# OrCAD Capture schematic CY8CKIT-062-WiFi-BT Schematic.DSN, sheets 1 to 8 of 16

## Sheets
1 01. Title Page: title: PSoC™ 6  Wi-Fi Bluetooth® Pioneer Kit; rev: 05; note: 630-60435-01
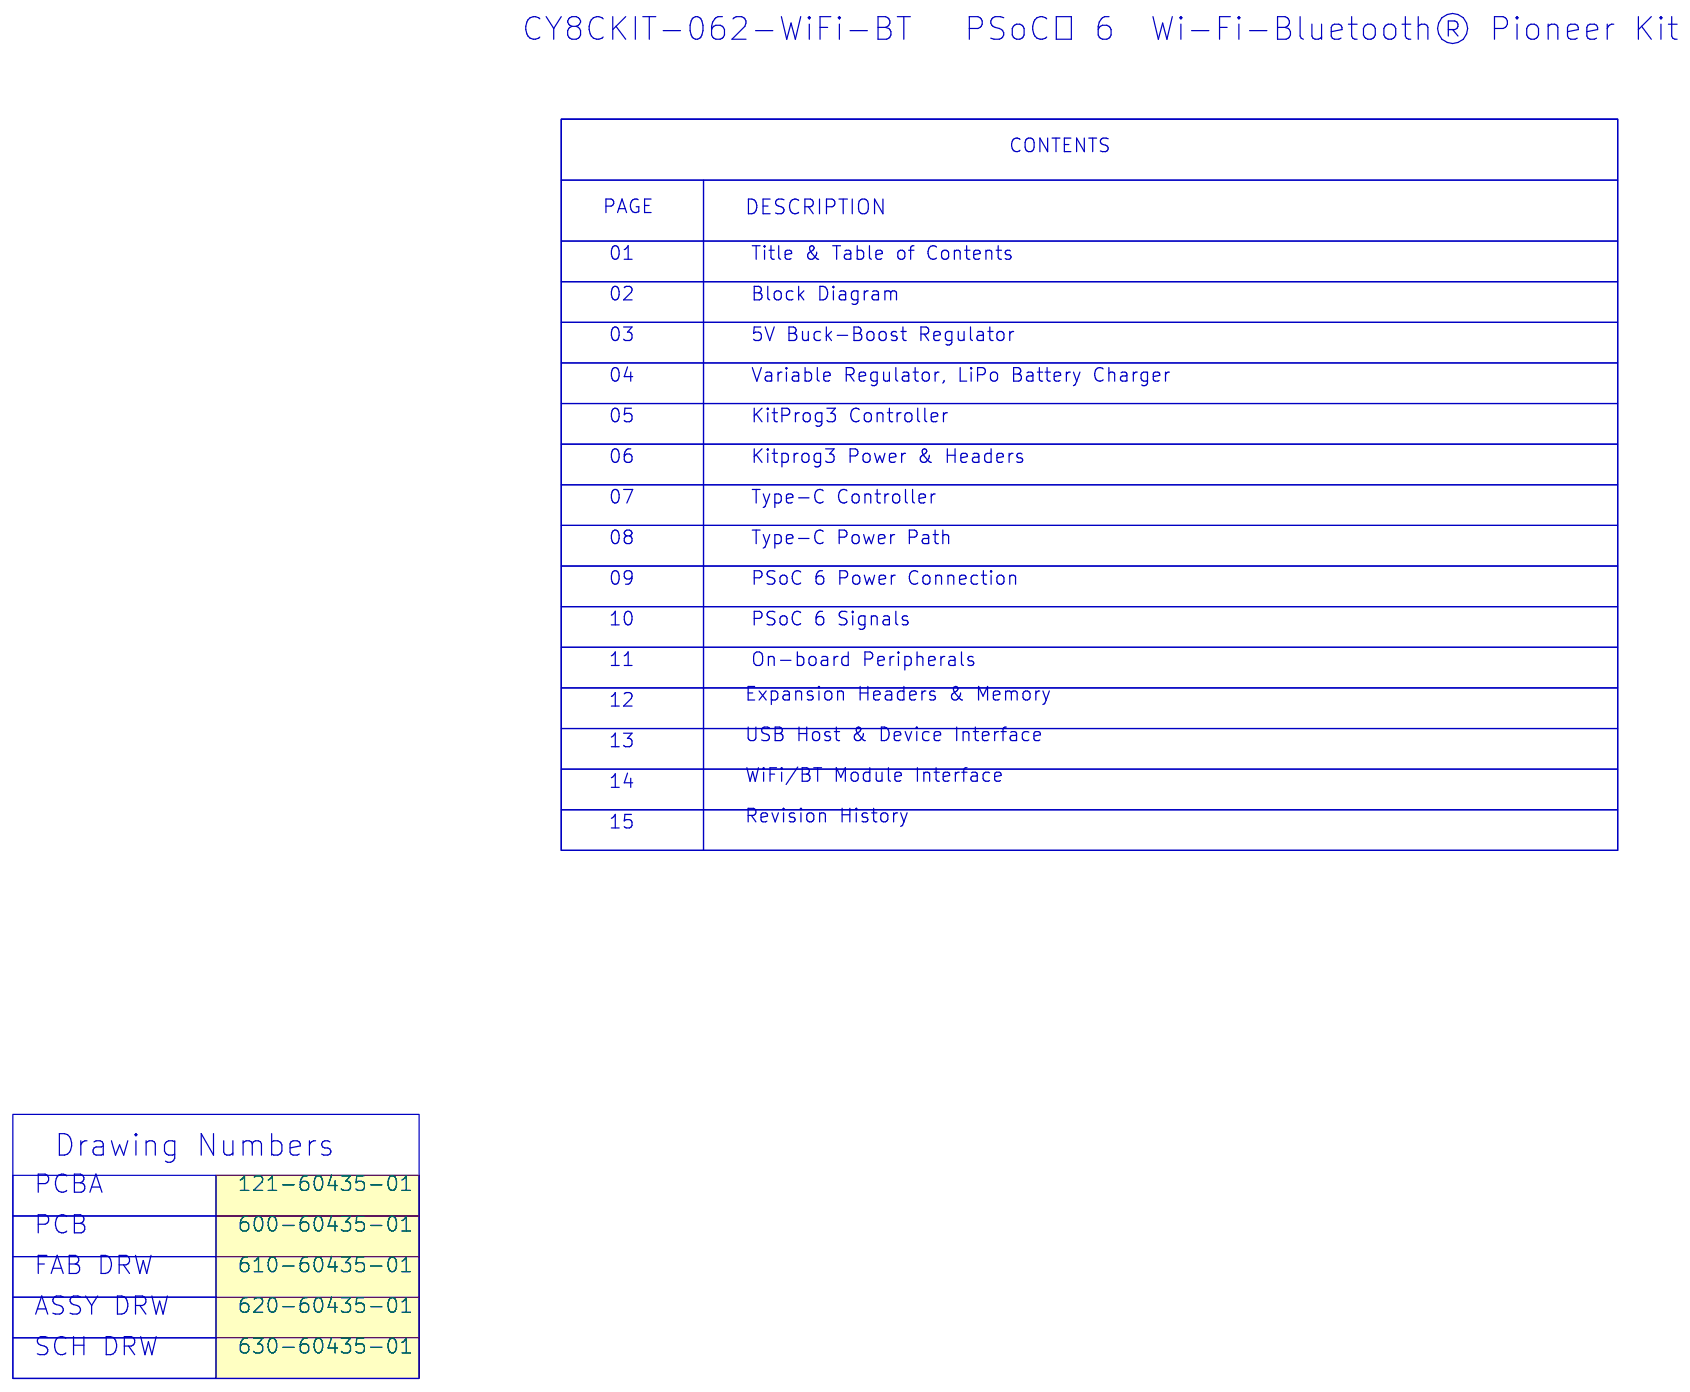
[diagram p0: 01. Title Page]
2 02. Block Diagram
3 04. Variable Regulator, Charger: size A4
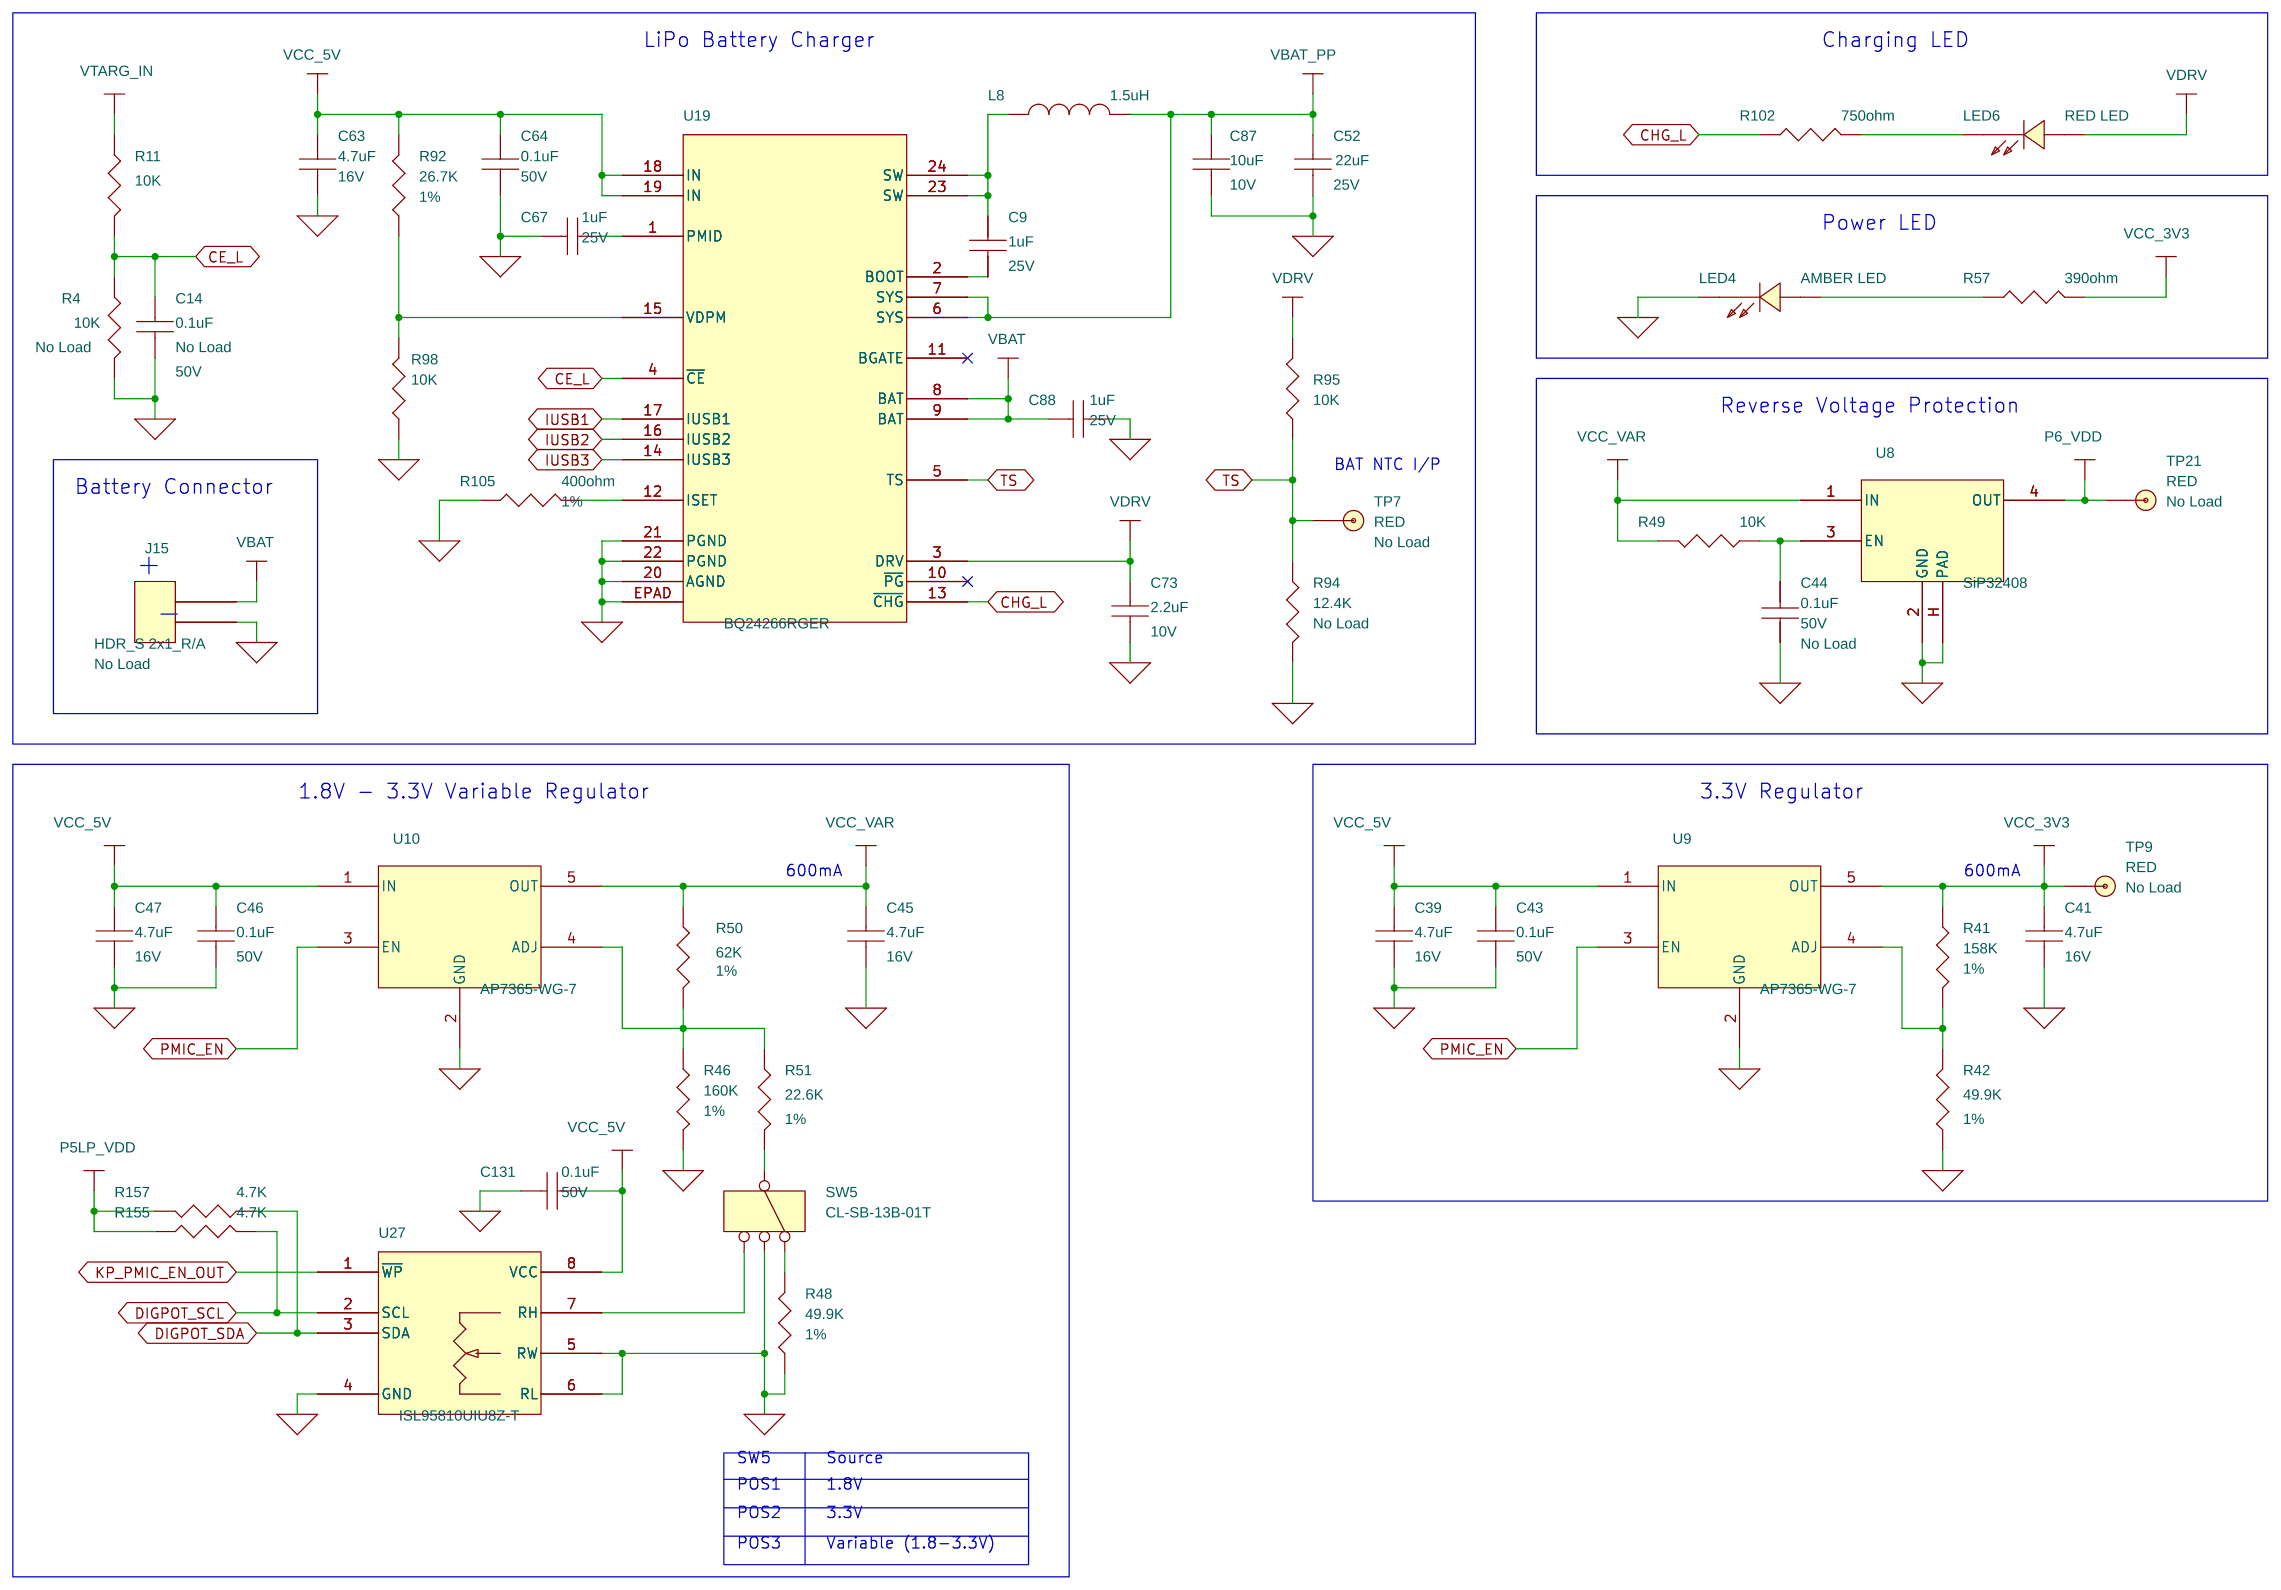
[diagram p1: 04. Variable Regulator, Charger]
4 05. KitProg3 Controller: size A4
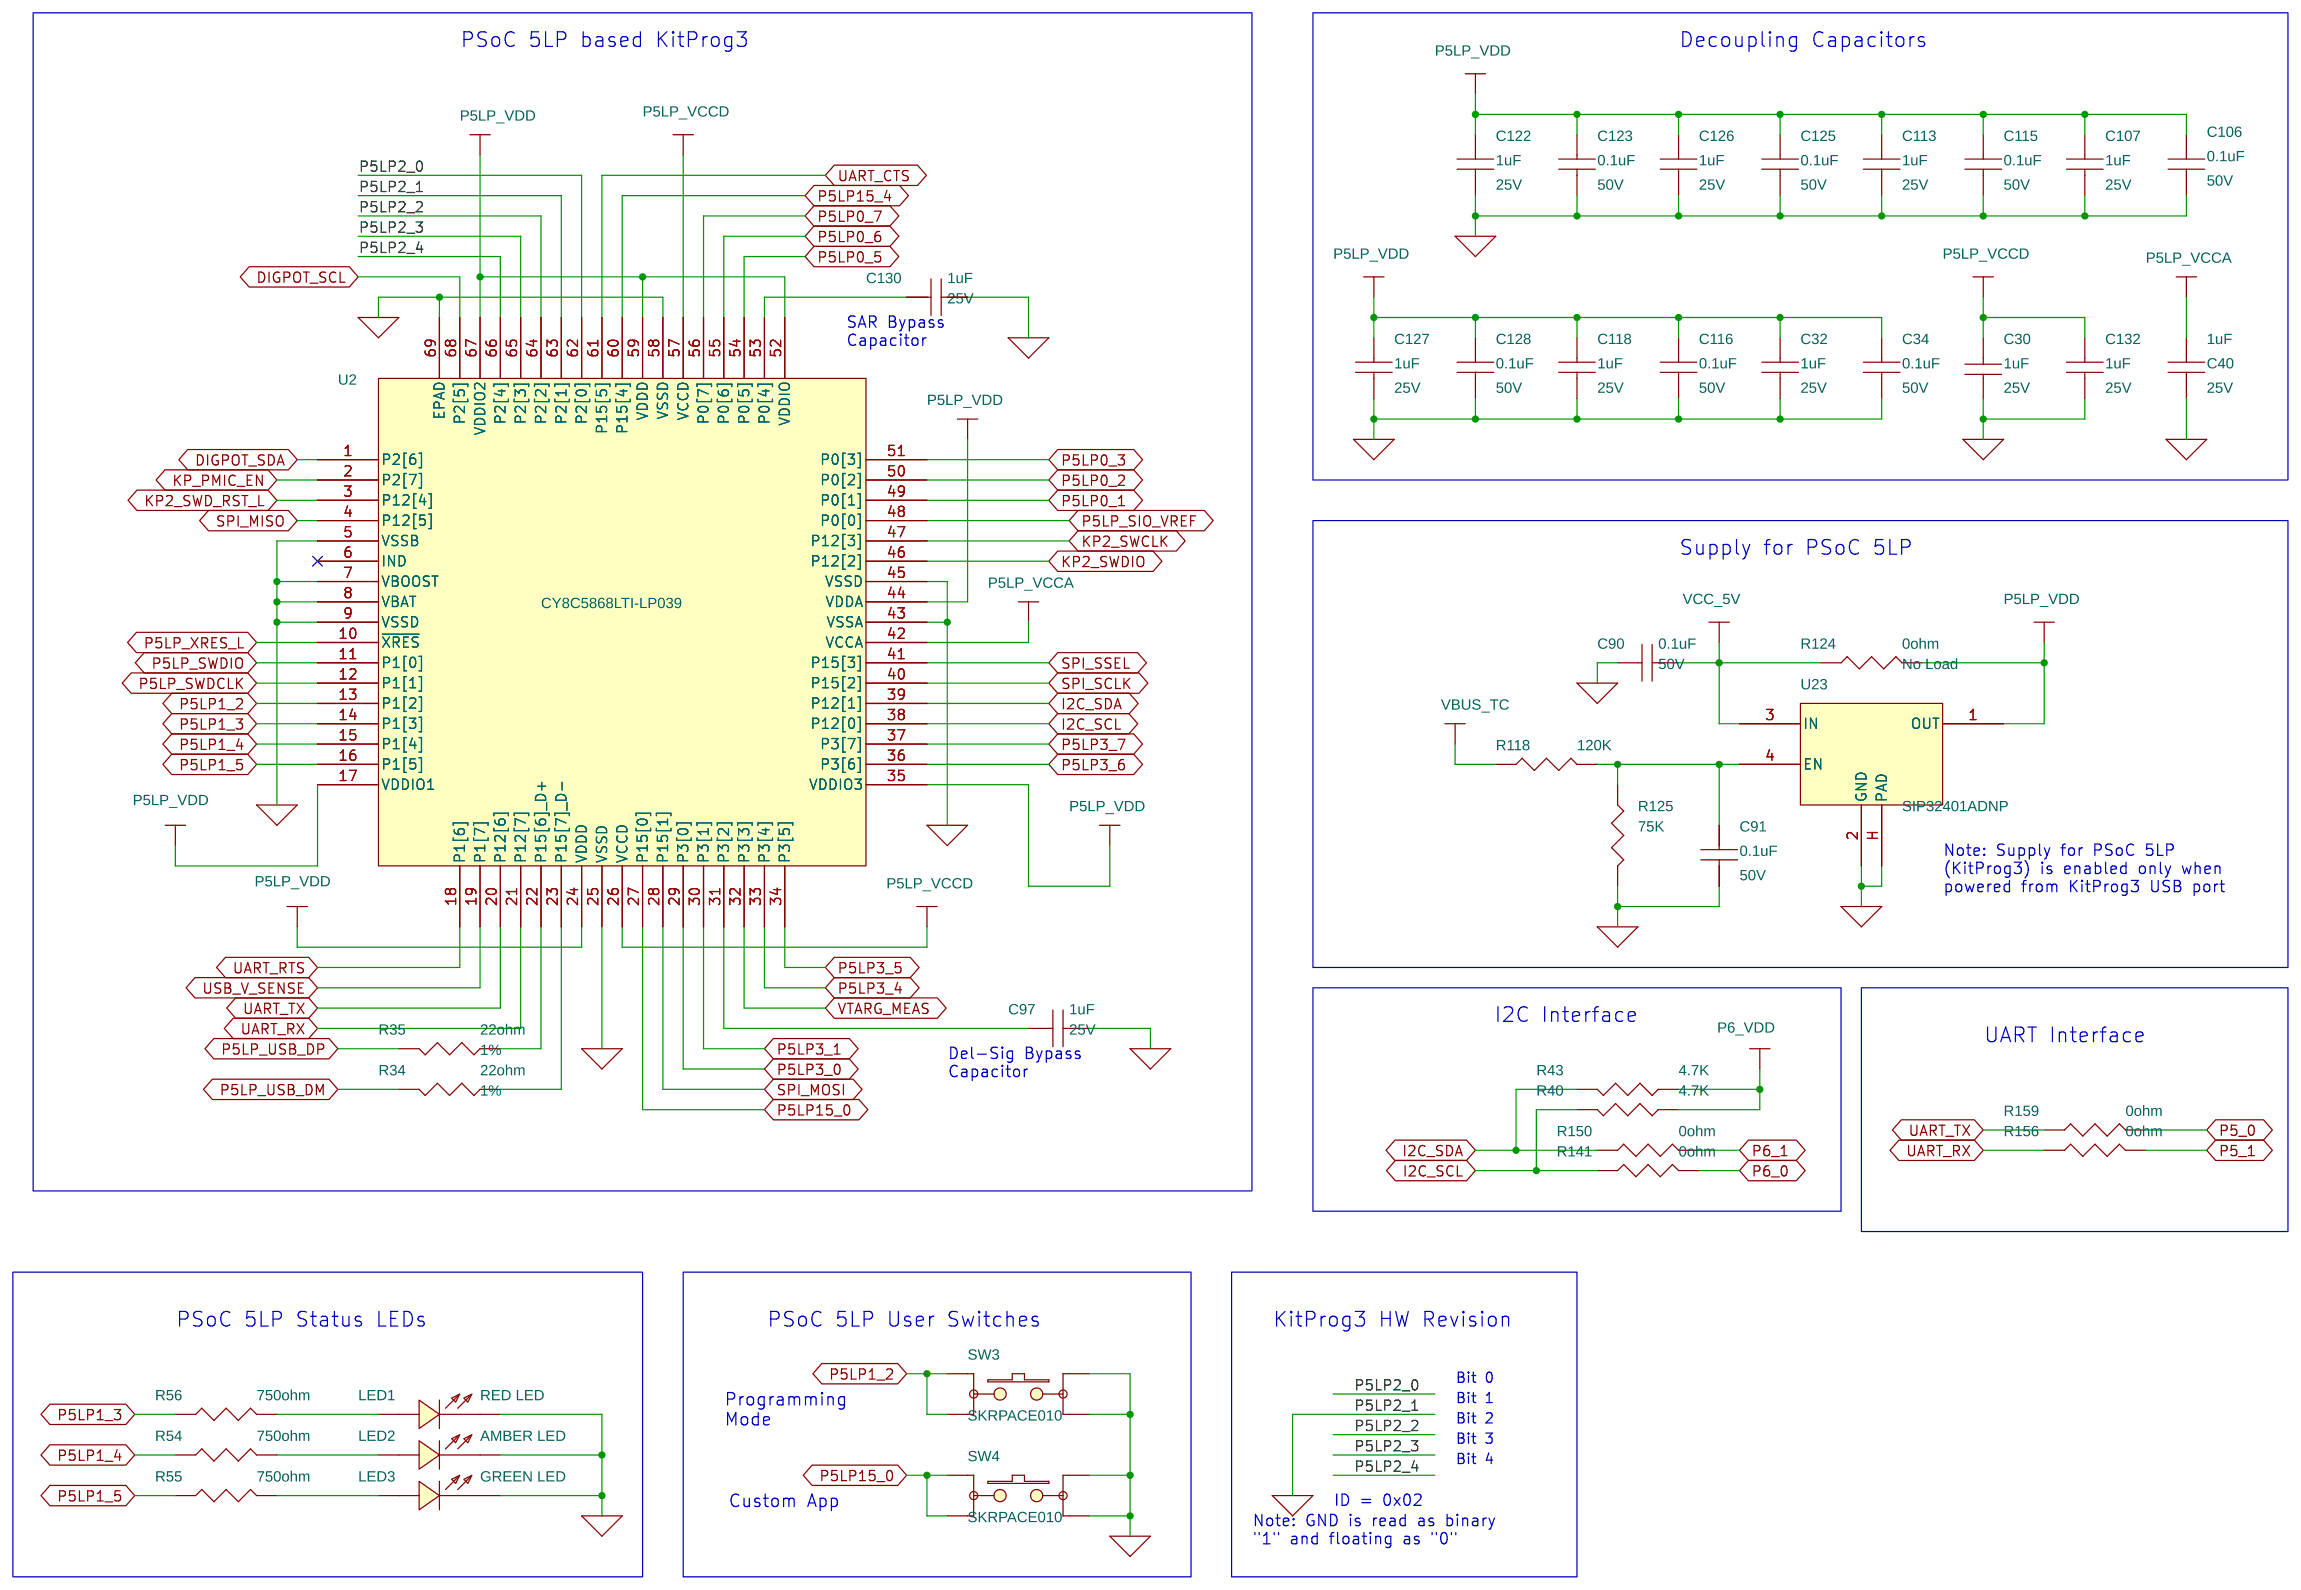
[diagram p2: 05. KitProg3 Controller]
5 06. Kitprog3 Power & Headers: size A4
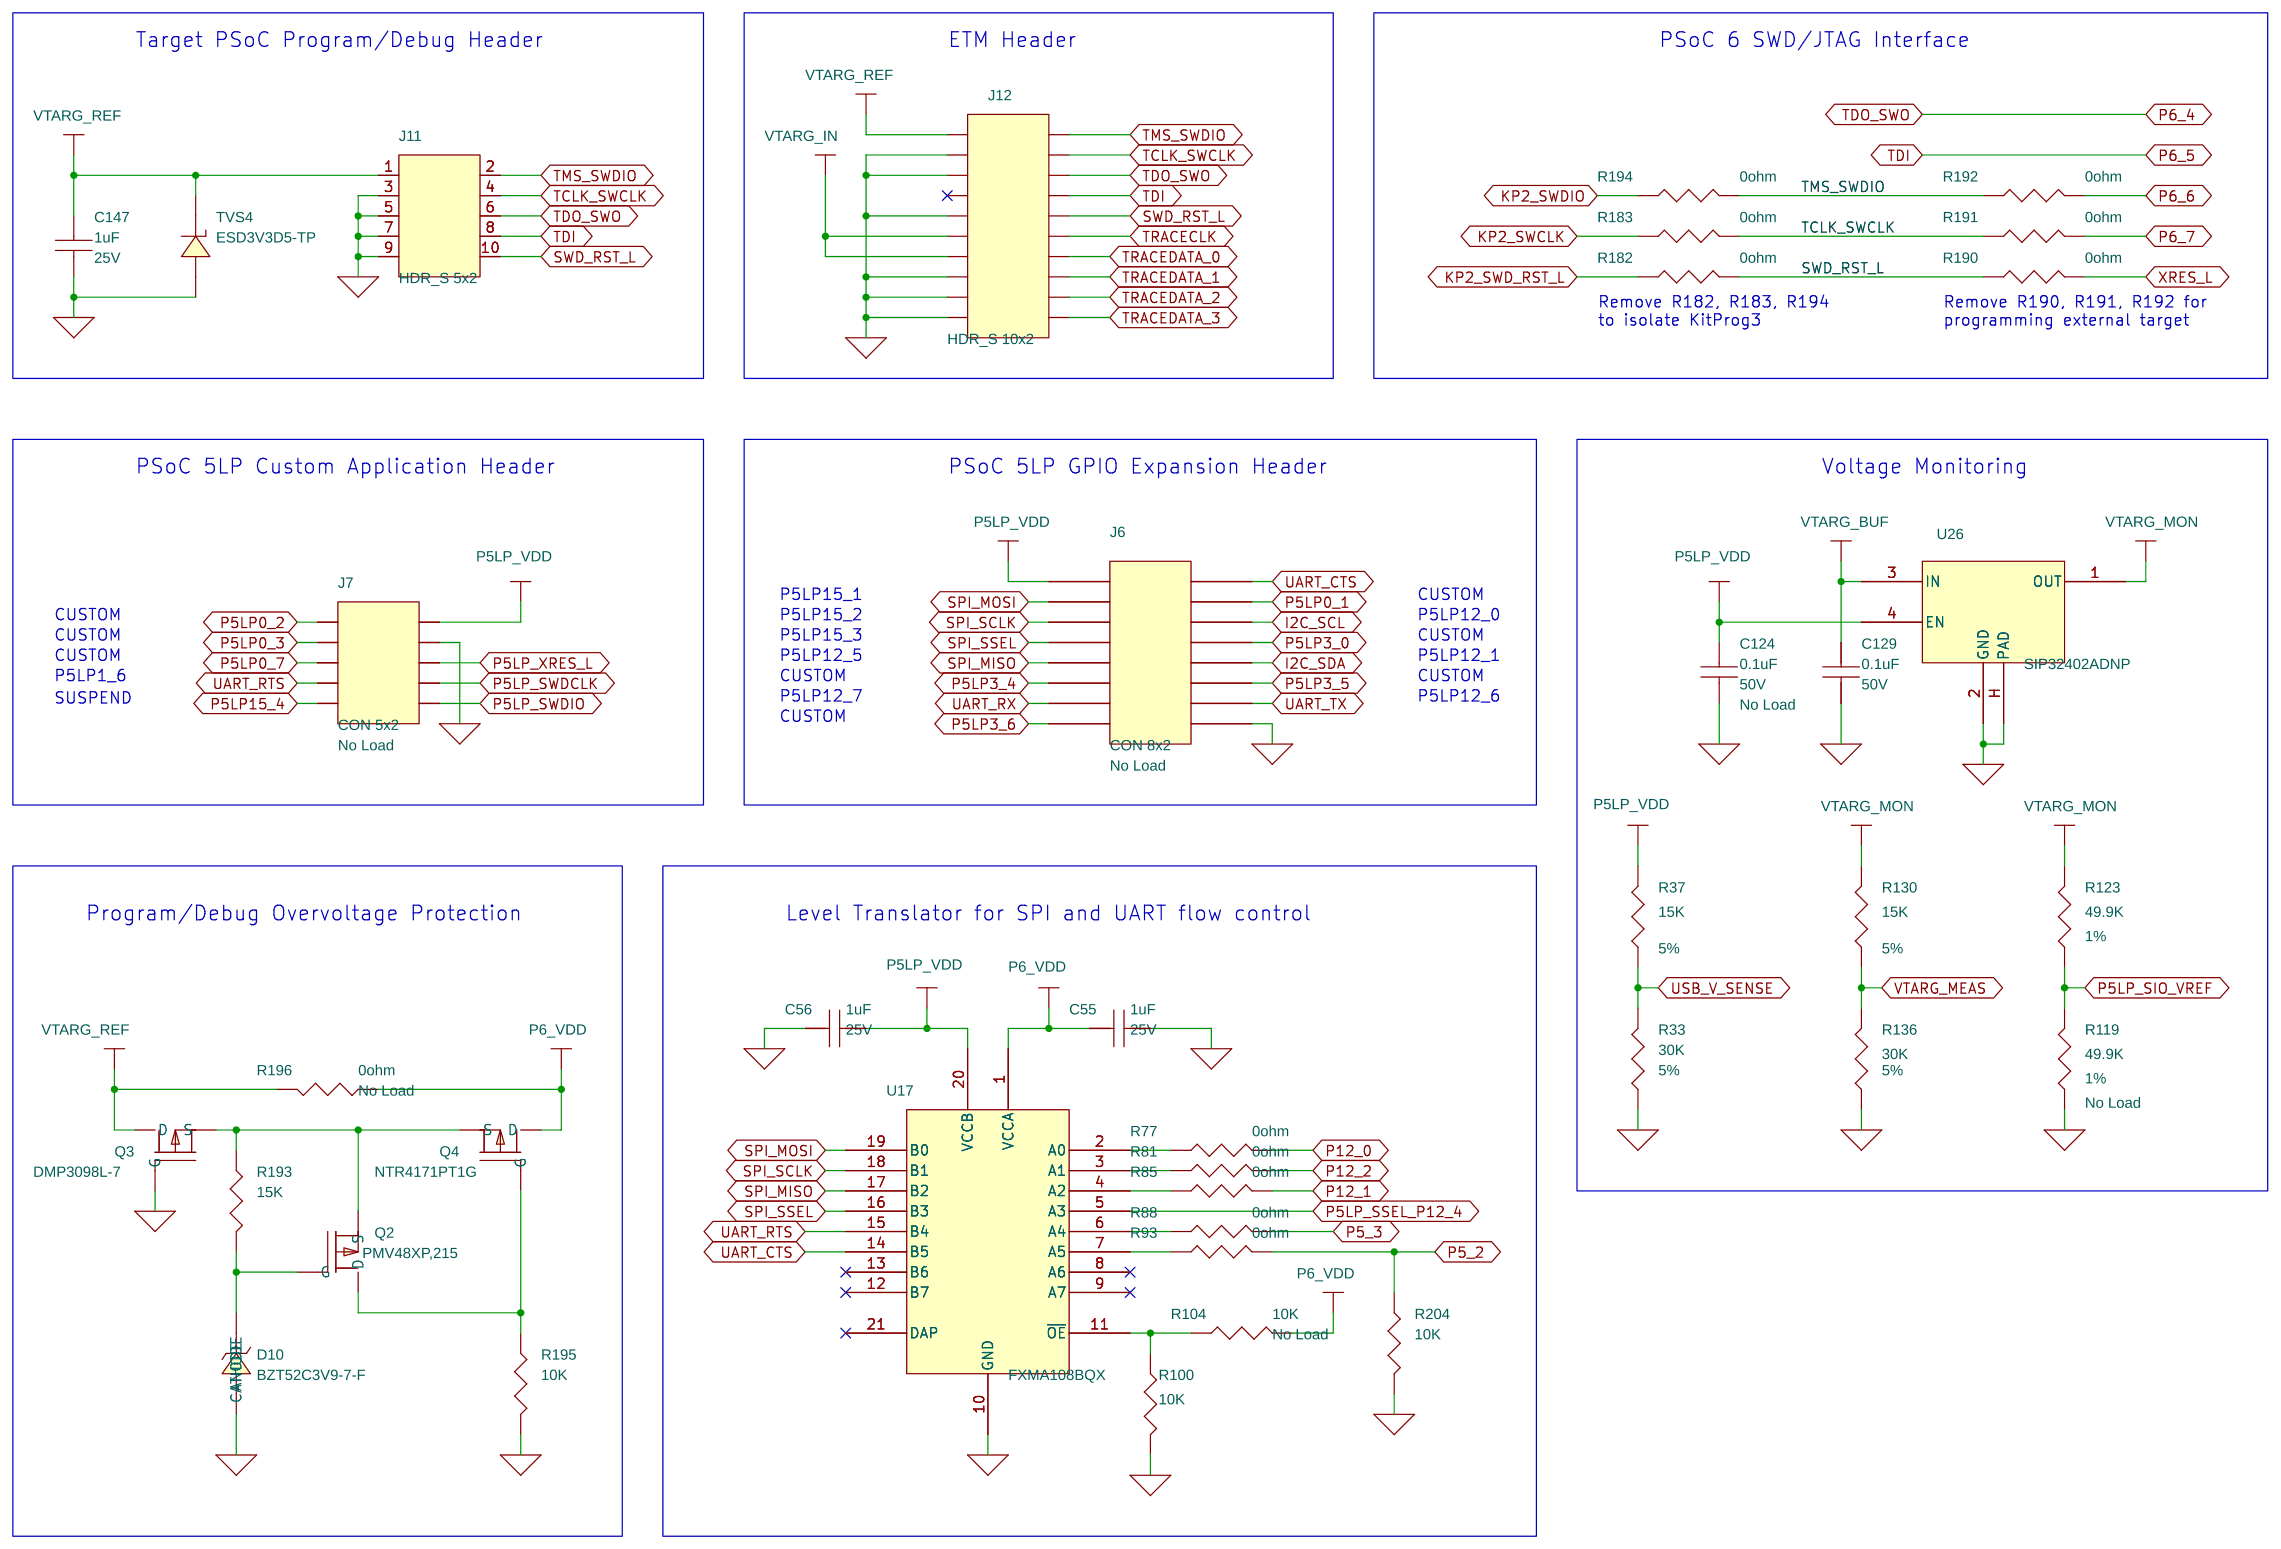
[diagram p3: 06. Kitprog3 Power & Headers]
6 07. Type-C Controller: size A4
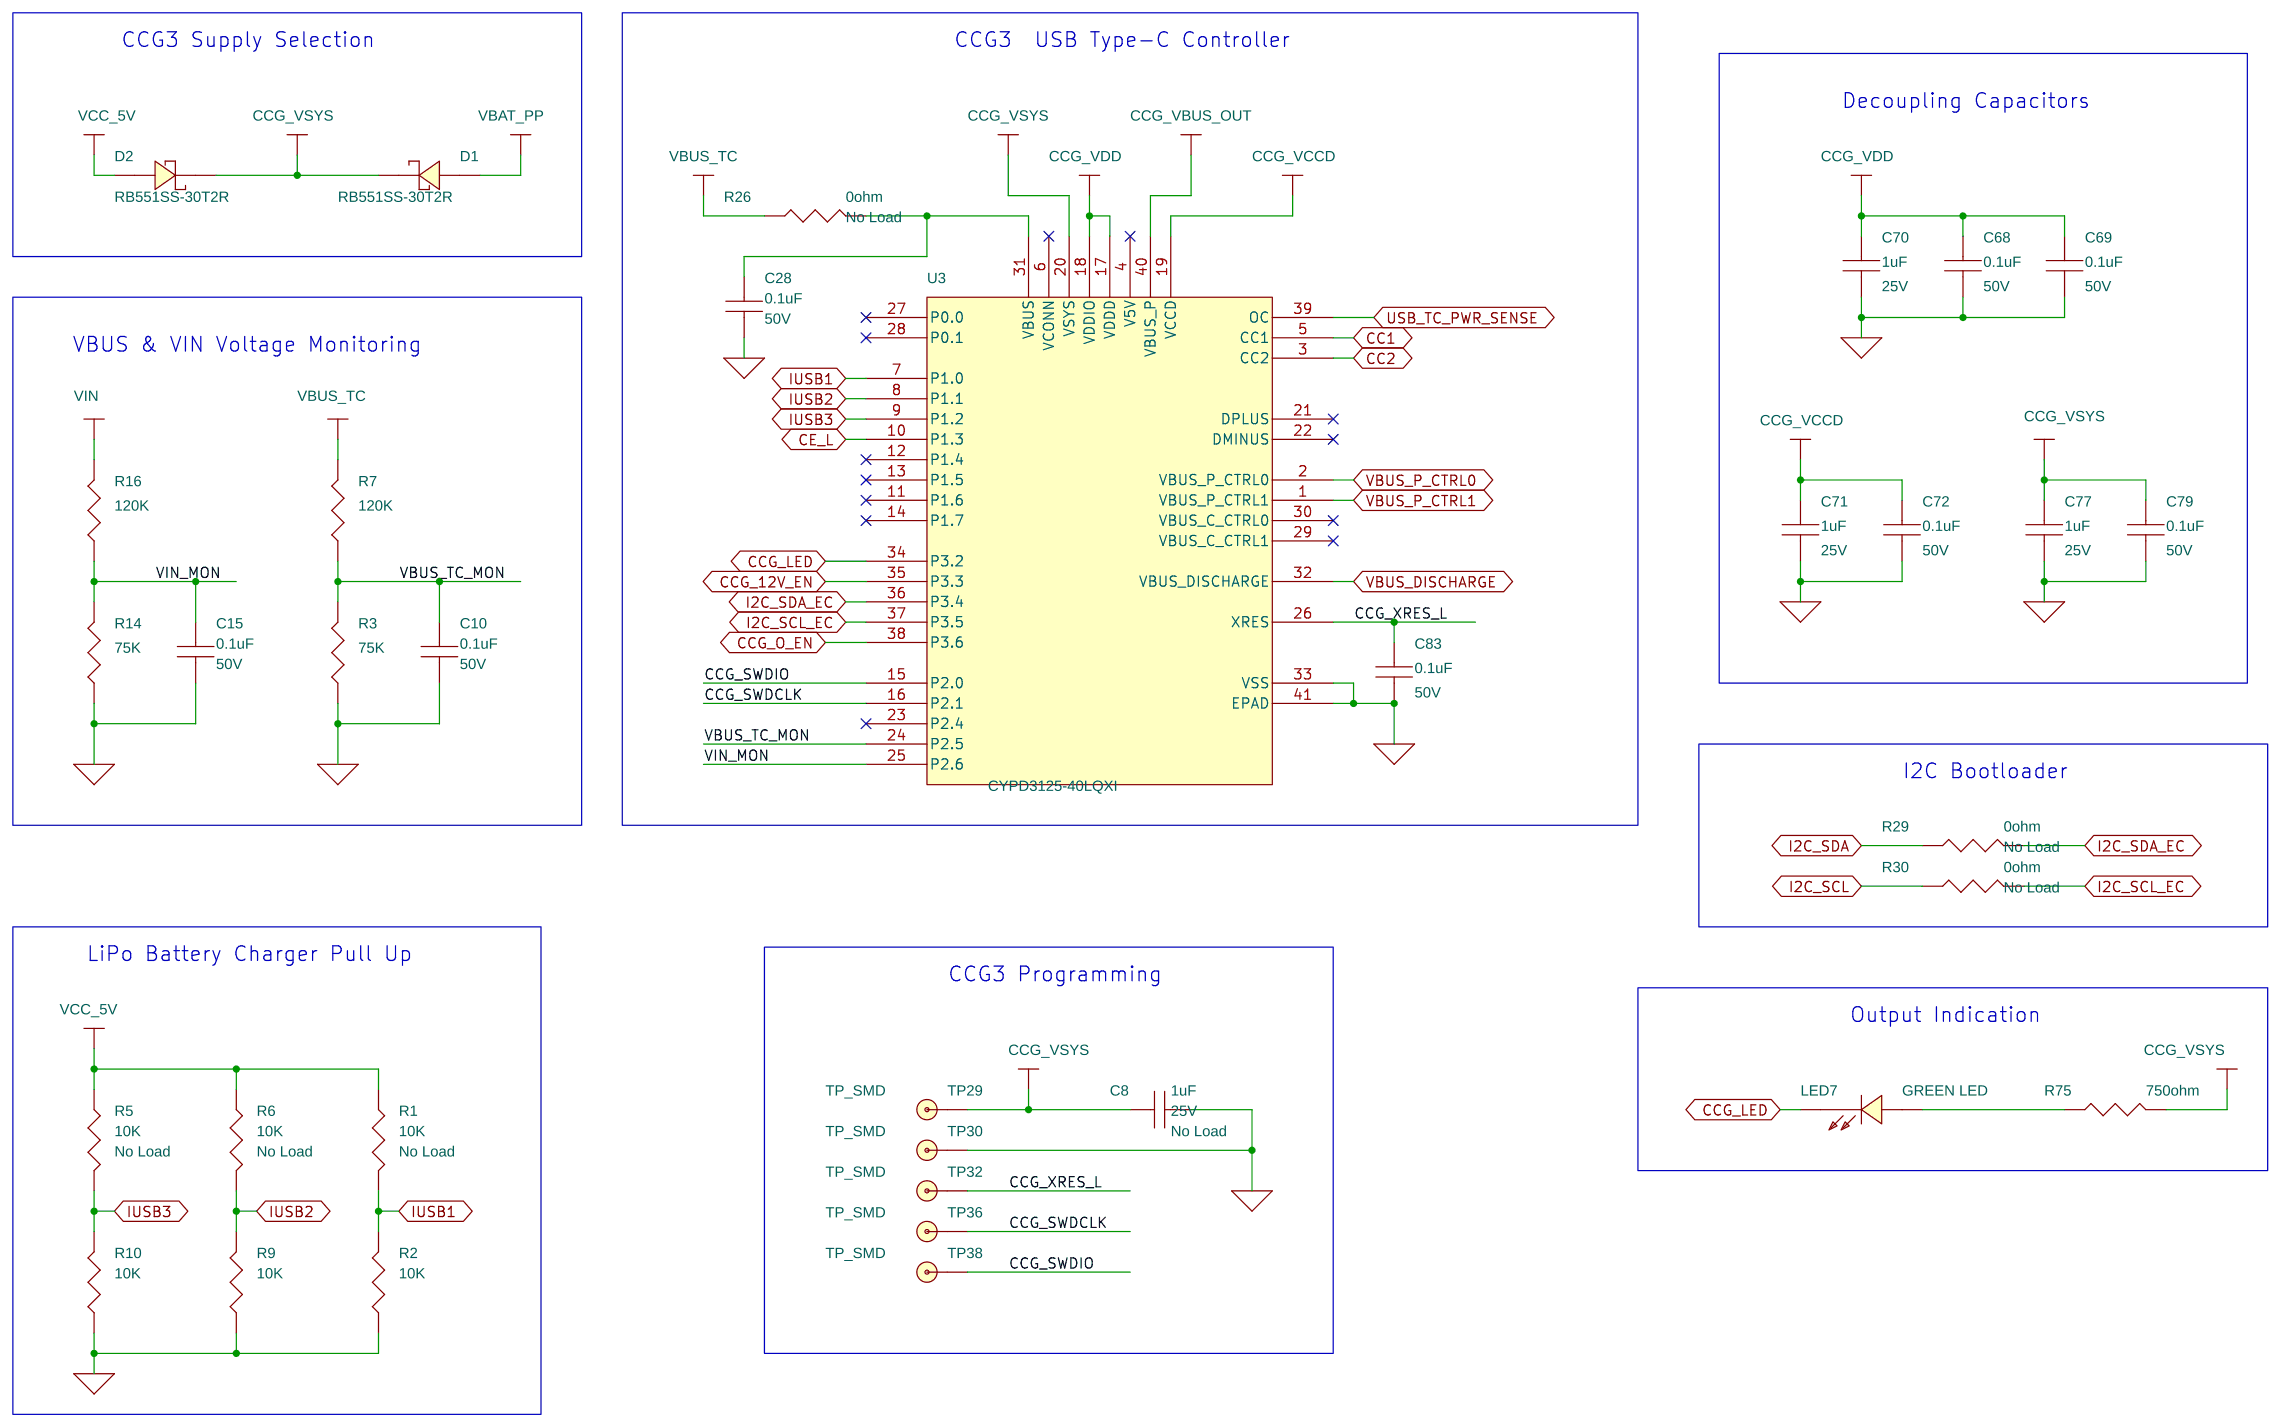
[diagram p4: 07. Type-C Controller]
7 08. Type-C Power Path: size A4
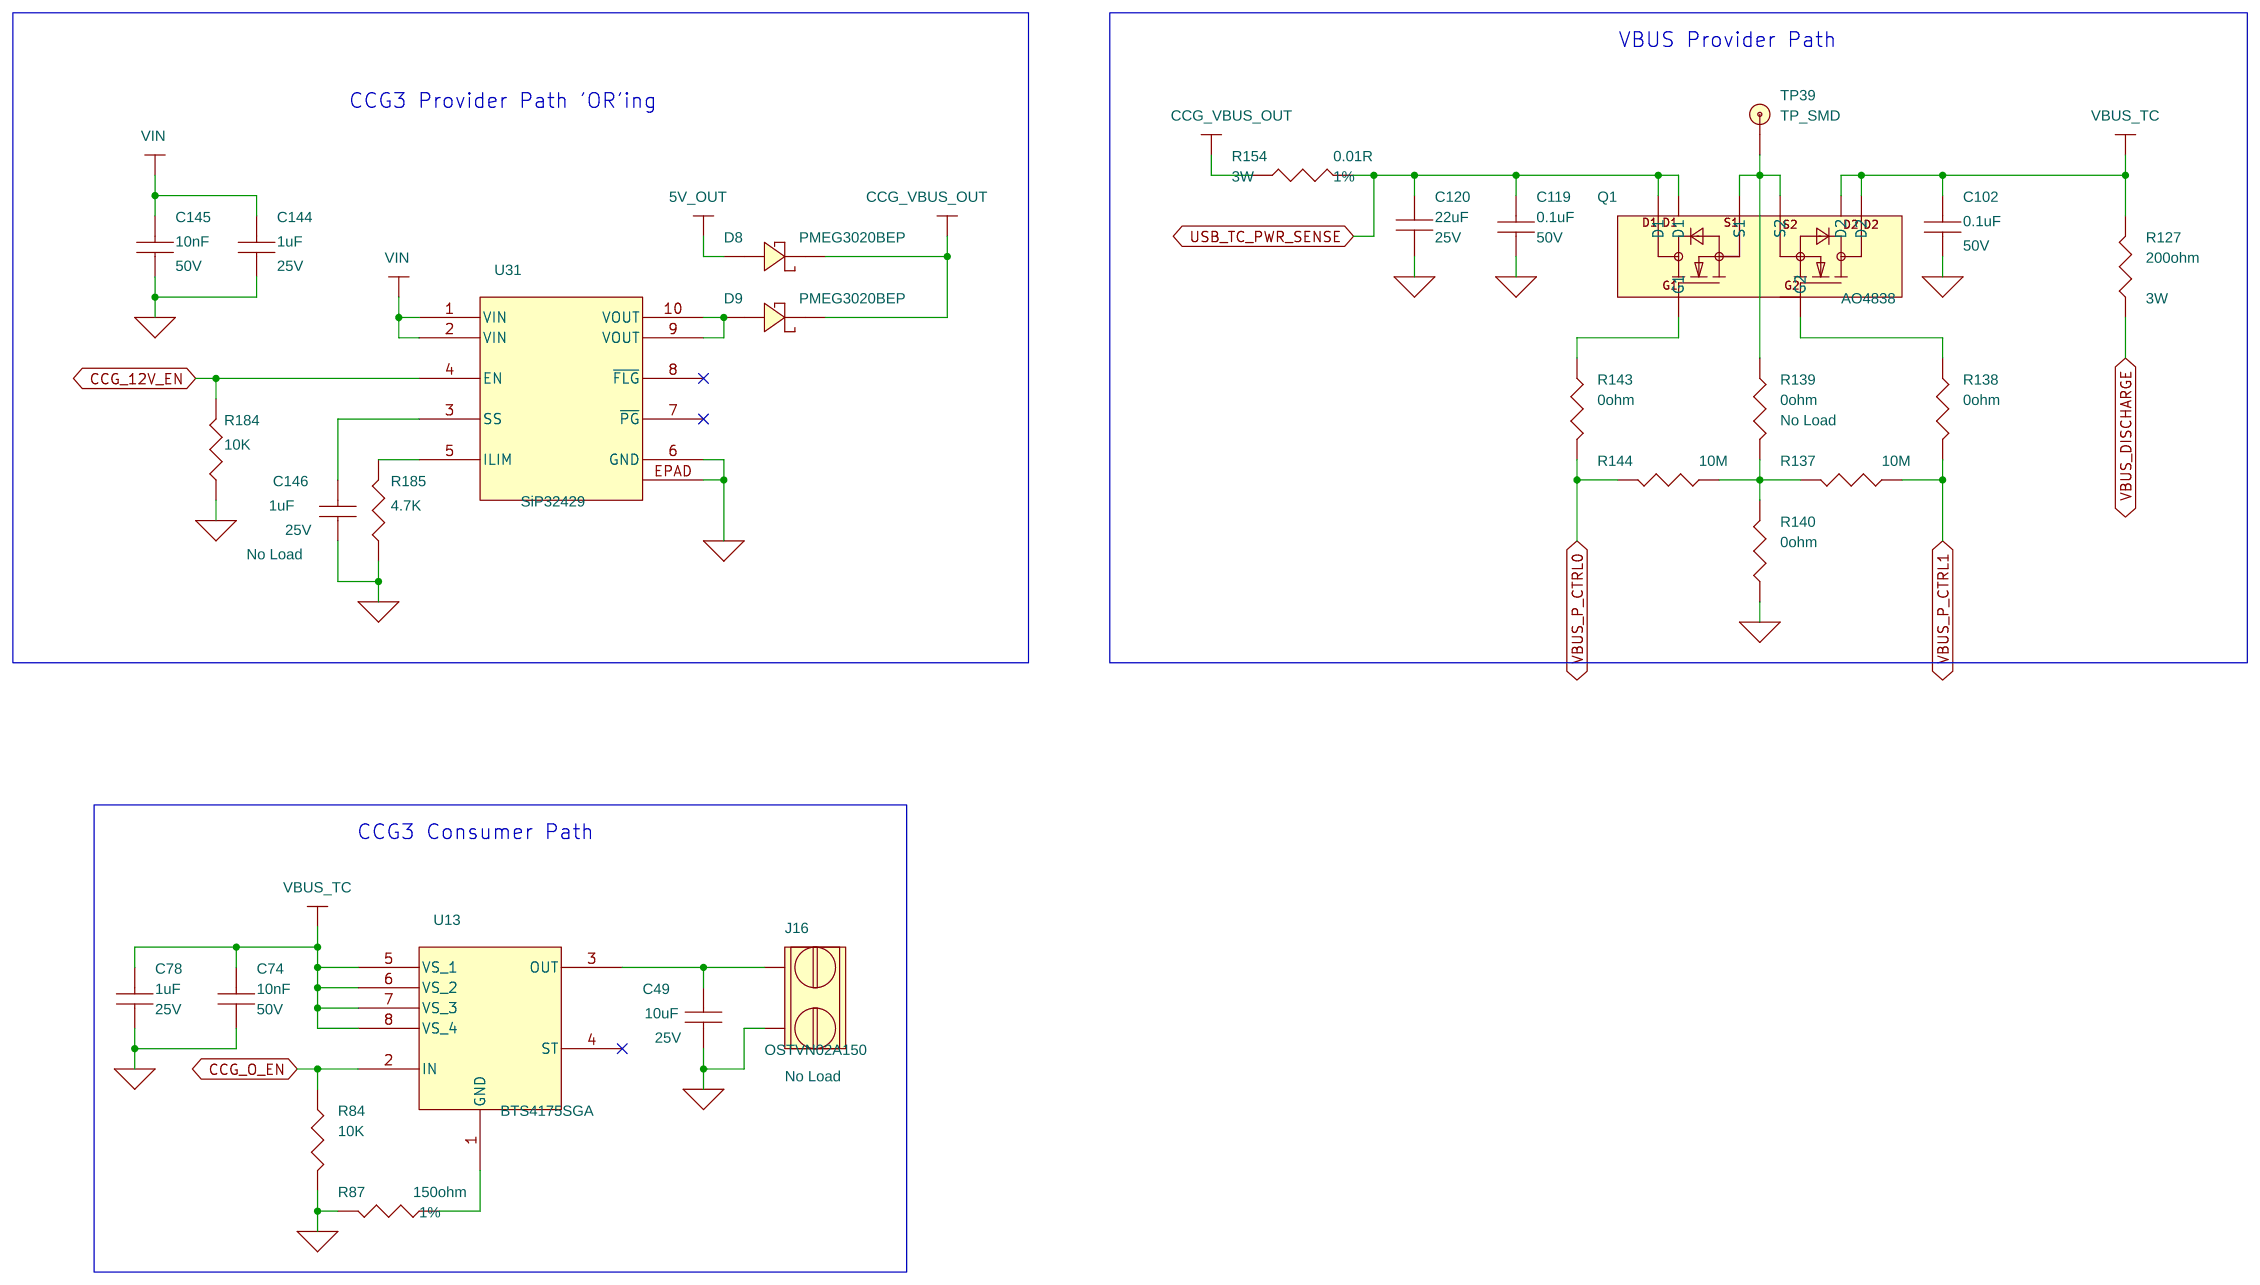
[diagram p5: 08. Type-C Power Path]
8 09. PSoC 6 Power: size A4
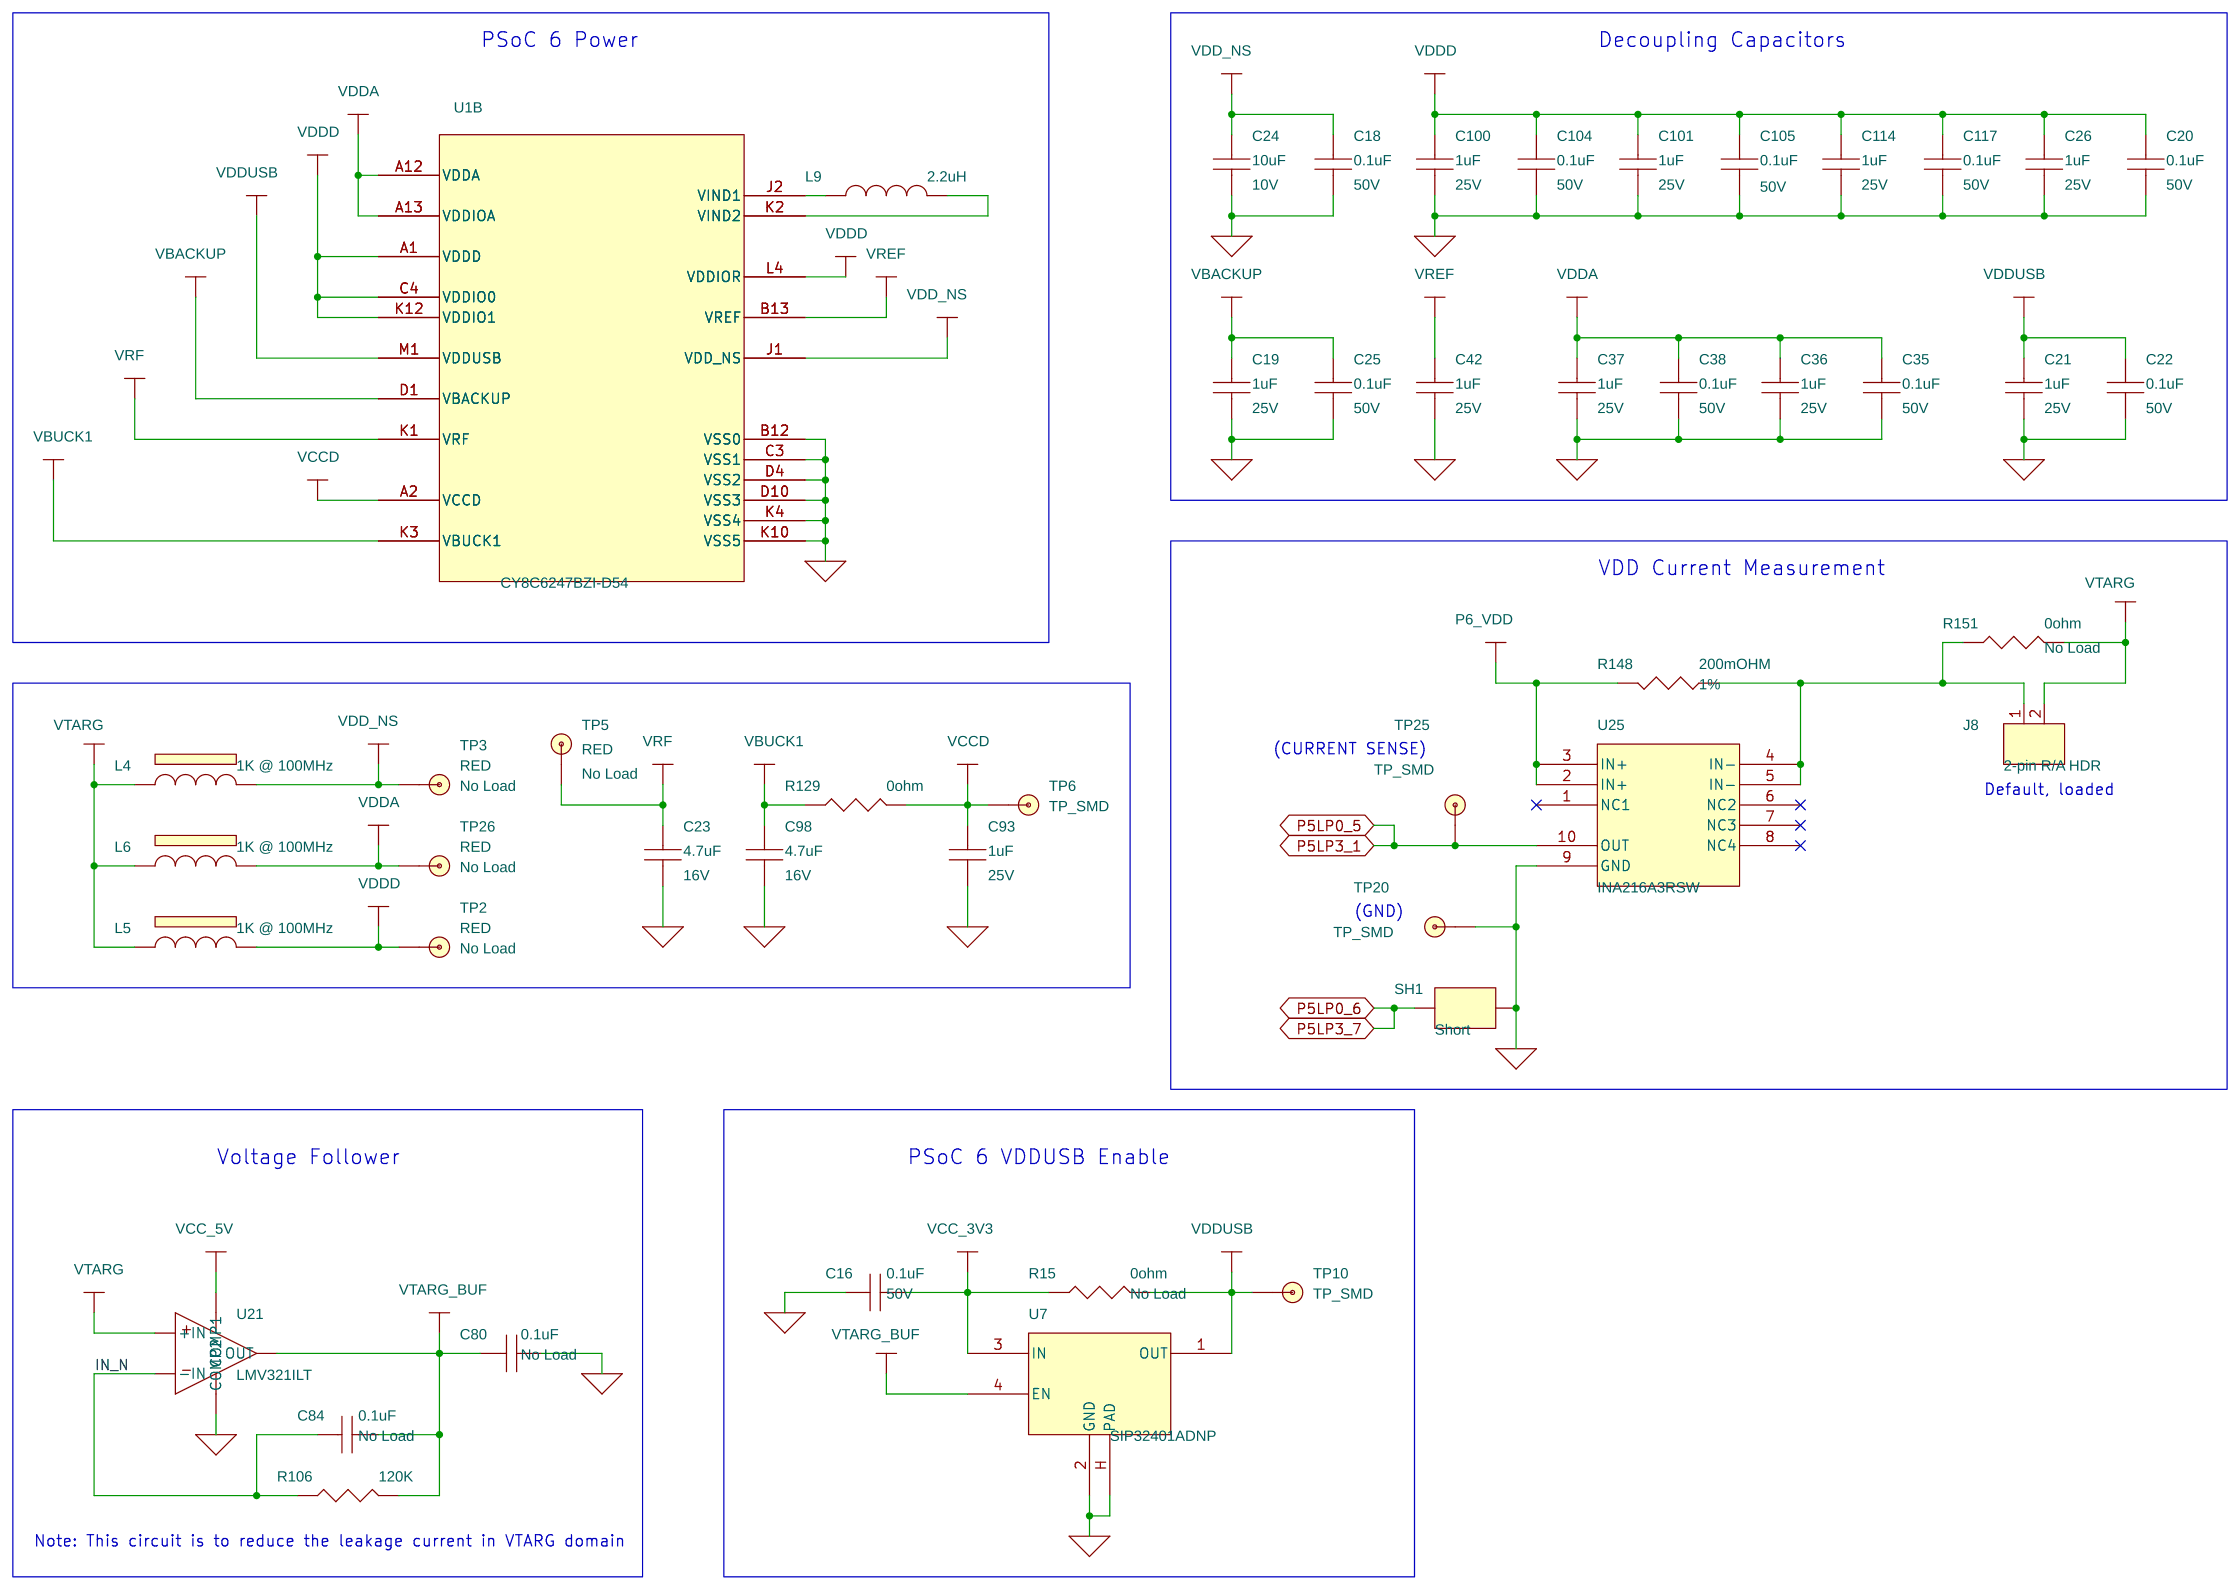
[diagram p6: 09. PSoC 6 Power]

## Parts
sheet 01. Title Page
ACC1  121-60435-01  [TBD]
ACC2  600-60435-01  [TBD]
ACC3  610-60435-01  [TBD]
ACC4  620-60435-01  [TBD]
ACC5  630-60435-01  [TBD]
sheet 04. Variable Regulator, Charger
C9  1uF  [CAPC1005X55M_D]
C14  0.1uF  [CAPC1005X55M_C]
C39  4.7uF  [CAPC1608X90M]
C41  4.7uF  [CAPC1608X90M]
C43  0.1uF  [CAPC1005X55M_D]
C44  0.1uF  [CAPC1005X55M_C]
C45  4.7uF  [CAPC1608X90M]
C46  0.1uF  [CAPC1005X55M_D]
C47  4.7uF  [CAPC1608X90M]
C52  22uF  [CAPC3216X180M_A]
C63  4.7uF  [CAPC1608X90M]
C64  0.1uF  [CAPC1005X55M_D]
C67  1uF  [CAPC1005X55M_D]
C73  2.2uF  [CAPC1005X55M]
C87  10uF  [CAPC1005X55M_D]
C88  1uF  [CAPC1005X55M_D]
C131  0.1uF  [CAPC1005X55M_D]
J15  HDR_S 2x1_R/A  [JST_S2B-PH-K-S]
L8  1.5uH  [INDM4242X200M]
LED4  AMBER LED  [LEDC2012X120M]
LED6  RED LED  [LEDC2012X120M]
R4  10K  [RESC1005X40M_A]
R11  10K  [RESC1005X40M_A]
R41  158K  [RESC1005X40M]
R42  49.9K  [RESC1005X40M_B]
R46  160K  [RESC1005X40M]
R48  49.9K  [RESC1005X40M_B]
R49  10K  [RESC1005X40M_A]
R50  62K  [RESC1005X40M]
R51  22.6K  [RESC1005X40M]
R57  390ohm  [RESC1005X40M_B]
R92  26.7K  [RESC1005X40M_A]
R94  12.4K  [RESC1005X40M_A]
R95  10K  [RESC1005X40M_A]
R98  10K  [RESC1005X40M_A]
R102  750ohm  [RESC1005X40M_B]
R105  400ohm  [RESC1005X40M_A]
R155  4.7K  [RESC1005X40M_A]
R157  4.7K  [RESC1005X40M_A]
SW5  CL-SB-13B-01T  [sw_cl-sb-13b-01t]
TP7  RED  [KEYSTONE_5000]
TP9  RED  [KEYSTONE_5000]
TP21  RED  [KEYSTONE_5000]
U8  SiP32408  [TDFN50P160X120X60-5M]
U9  AP7365-WG-7  [SOT95P285X140-5M]
U10  AP7365-WG-7  [SOT95P285X140-5M]
U19  BQ24266RGER  [QFN50P400X400X100-25M]
U27  ISL95810UIU8Z-T  [MSOP65P490X110-8M]
sheet 05. KitProg3 Controller
C30  1uF  [CAPC1005X55M_D]
C32  1uF  [CAPC1005X55M_D]
C34  0.1uF  [CAPC1005X55M_C]
C40  1uF  [CAPC1005X55M_D]
C90  0.1uF  [CAPC1005X55M_C]
C91  0.1uF  [CAPC1005X55M_C]
C97  1uF  [CAPC1005X55M_D]
C106  0.1uF  [CAPC1005X55M_C]
C107  1uF  [CAPC1005X55M_D]
C113  1uF  [CAPC1005X55M_D]
C115  0.1uF  [CAPC1005X55M_C]
C116  0.1uF  [CAPC1005X55M_C]
C118  1uF  [CAPC1005X55M_D]
C122  1uF  [CAPC1005X55M_D]
C123  0.1uF  [CAPC1005X55M_C]
C125  0.1uF  [CAPC1005X55M_C]
C126  1uF  [CAPC1005X55M_D]
C127  1uF  [CAPC1005X55M_D]
C128  0.1uF  [CAPC1005X55M_C]
C130  1uF  [CAPC1005X55M_D]
C132  1uF  [CAPC1005X55M_D]
LED1  RED LED  [LEDC2012X120M]
LED2  AMBER LED  [LEDC2012X120M]
LED3  GREEN LED  [LEDC2012X120M]
R34  22ohm  [RESC1005X40M_A]
R35  22ohm  [RESC1005X40M_A]
R40  4.7K  [RESC1005X40M_A]
R43  4.7K  [RESC1005X40M_A]
R54  750ohm  [RESC1005X40M_B]
R55  750ohm  [RESC1005X40M_B]
R56  750ohm  [RESC1005X40M_B]
R118  120K  [RESC1005X40M_A]
R124  0ohm  [RESC1608X55M_A]
R125  75K  [RESC1005X40M_A]
R141  0ohm  [RESC1608X55M_A]
R150  0ohm  [RESC1608X55M_A]
R156  0ohm  [RESC1608X55M_A]
R159  0ohm  [RESC1608X55M_A]
SW3  SKRPACE010  [SW_SKRPACE010]
SW4  SKRPACE010  [SW_SKRPACE010]
U2  CY8C5868LTI-LP039  [QFN40P800X800X100-69M]
U23  SIP32401ADNP  [TDFN50P160X120X60-5M]
sheet 06. Kitprog3 Power & Headers
C55  1uF  [CAPC1005X55M_D]
C56  1uF  [CAPC1005X55M_D]
C124  0.1uF  [CAPC1005X55M_C]
C129  0.1uF  [CAPC1005X55M_C]
C147  1uF  [CAPC1005X55M_D]
D10  BZT52C3V9-7-F  [SOD3715X145M]
J6  CON 8x2  [SULLINS_PPPC082LFBN-R_FLIP]
J7  CON 5x2  [SULLINS_PPPC052LFBN-RC_flip]
J11  HDR_S 5x2  [CNC_3220-10-0100-00]
J12  HDR_S 10x2  [cnctech_3220-20-0100-00]
Q2  PMV48XP,215  [SOT95P230X110-3M]
Q3  DMP3098L-7  [SOT92P240X110-3M]
Q4  NTR4171PT1G  [SOT95P237X111-3M_A]
R33  30K  [RESC1005X40M_B]
R37  15K  [RESC1005X40M_B]
R77  0ohm  [RESC1608X55M_A]
R81  0ohm  [RESC1608X55M_A]
R85  0ohm  [RESC1608X55M_A]
R88  0ohm  [RESC1608X55M_A]
R93  0ohm  [RESC1608X55M_A]
R100  10K  [RESC1005X40M_A]
R104  10K  [RESC1005X40M_A]
R119  49.9K  [RESC1005X40M_B]
R123  49.9K  [RESC1005X40M_B]
R130  15K  [RESC1005X40M_B]
R136  30K  [RESC1005X40M_B]
R182  0ohm  [RESC1608X55M_A]
R183  0ohm  [RESC1608X55M_A]
R190  0ohm  [RESC1608X55M_A]
R191  0ohm  [RESC1608X55M_A]
R192  0ohm  [RESC1608X55M_A]
R193  15K  [RESC1005X40M_B]
R194  0ohm  [RESC1608X55M_A]
R195  10K  [RESC1005X40M_A]
R196  0ohm  [RESC1608X55M_A]
R204  10K  [RESC1005X40M_A]
TVS4  ESD3V3D5-TP  [SODFL1608X77M]
U17  FXMA108BQX  [DQFN50P250X450X80-21M]
U26  SIP32402ADNP  [TDFN50P160X120X60-5M]
sheet 07. Type-C Controller
C8  1uF  [CAPC1005X55M_D]
C10  0.1uF  [CAPC1005X55M_C]
C15  0.1uF  [CAPC1005X55M_C]
C28  0.1uF  [CAPC1005X55M_C]
C68  0.1uF  [CAPC1005X55M_C]
C69  0.1uF  [CAPC1005X55M_C]
C70  1uF  [CAPC1005X55M_D]
C71  1uF  [CAPC1005X55M_D]
C72  0.1uF  [CAPC1005X55M_C]
C77  1uF  [CAPC1005X55M_D]
C79  0.1uF  [CAPC1005X55M_C]
C83  0.1uF  [CAPC1005X55M_C]
D1  RB551SS-30T2R  [DIO160X80X63-2M]
D2  RB551SS-30T2R  [DIO160X80X63-2M]
LED7  GREEN LED  [LEDC2012X120M]
R1  10K  [RESC1005X40M_A]
R2  10K  [RESC1005X40M_A]
R3  75K  [RESC1005X40M_A]
R5  10K  [RESC1005X40M_A]
R6  10K  [RESC1005X40M_A]
R7  120K  [RESC1005X40M_B]
R9  10K  [RESC1005X40M_A]
R10  10K  [RESC1005X40M_A]
R14  75K  [RESC1005X40M_A]
R16  120K  [RESC1005X40M_B]
R26  0ohm  [RESC1608X55M_A]
R29  0ohm  [RESC1608X55M_A]
R30  0ohm  [RESC1608X55M_A]
R75  750ohm  [RESC1005X40M_B]
TP29  TP_SMD  [TP50_12D_24BOT_MIL]
TP30  TP_SMD  [TP50_12D_24BOT_MIL]
TP32  TP_SMD  [TP50_12D_24BOT_MIL]
TP36  TP_SMD  [TP50_12D_24BOT_MIL]
TP38  TP_SMD  [TP50_12D_24BOT_MIL]
U3  CYPD3125-40LQXI  [QFN50P600X600X60-41M]
sheet 08. Type-C Power Path
C49  10uF  [CAPC2012X140M]
C74  10nF  [CAPC1005X55M_C]
C78  1uF  [CAPC1005X55M_D]
C102  0.1uF  [CAPC1005X55M_C]
C119  0.1uF  [CAPC1005X55M_C]
C120  22uF  [CAPC2012X140M]
C144  1uF  [CAPC1005X55M_D]
C145  10nF  [CAPC1005X55M_C]
C146  1uF  [CAPC1005X55M_D]
D8  PMEG3020BEP  [SODFL4725X110M]
D9  PMEG3020BEP  [SODFL4725X110M]
J16  OSTVN02A150  [OST_OSTVN02A150]
Q1  AO4838  [SOIC127P600X175-8M]
R84  10K  [RESC1005X40M_A]
R87  150ohm  [RESC1005X40M_A]
R127  200ohm  [RESC6432X120M]
R137  10M  [RESC1005X40M]
R138  0ohm  [RESC1608X55M_A]
R139  0ohm  [RESC1608X55M_A]
R140  0ohm  [RESC1005X40M]
R143  0ohm  [RESC1608X55M_A]
R144  10M  [RESC1005X40M]
R154  0.01R  [RESC6432X120M]
R184  10K  [RESC1005X40M_A]
R185  4.7K  [RESC1005X40M_A]
TP39  TP_SMD  [TP102C]
U13  BTS4175SGA  [SOIC127P600X175-8M]
U31  SiP32429  [SON50P300X300X100-11M_VS]
sheet 09. PSoC 6 Power
C16  0.1uF  [CAPC1005X55M_C]
C18  0.1uF  [CAPC1005X55m]
C19  1uF  [CAPC1005X55M]
C20  0.1uF  [CAPC1005X55m]
C21  1uF  [CAPC1005X55M]
C22  0.1uF  [CAPC1005X55m]
C23  4.7uF  [CAPC1005X55M]
C24  10uF  [CAPC1005X55M]
C25  0.1uF  [CAPC1005X55m]
C26  1uF  [CAPC1005X55M]
C35  0.1uF  [CAPC1005X55m]
C36  1uF  [CAPC1005X55M]
C37  1uF  [CAPC1005X55M]
C38  0.1uF  [CAPC1005X55m]
C42  1uF  [CAPC1005X55M]
C80  0.1uF  [CAPC1005X55M_C]
C84  0.1uF  [CAPC1005X55M_C]
C93  1uF  [CAPC1005X55M]
C98  4.7uF  [CAPC1005X55M]
C100  1uF  [CAPC1005X55M]
C101  1uF  [CAPC1005X55M]
C104  0.1uF  [CAPC1005X55m]
C105  0.1uF  [CAPC1005X55m]
C114  1uF  [CAPC1005X55M]
C117  0.1uF  [CAPC1005X55m]
J8  2-pin R/A HDR  [HARWIN_M20-9960245]
L4  1K @ 100MHz  [INDC2012X105M]
L5  1K @ 100MHz  [INDC2012X105M]
L6  1K @ 100MHz  [INDC2012X105M]
L9  2.2uH  [INDC2016X100M]
R15  0ohm  [RESC1608X55M_A]
R106  120K  [RESC1005X40M_A]
R129  0ohm  [RESC1005X40M]
R148  200mOHM  [RESC1005X40M_A]
R151  0ohm  [RESC1608X55M_A]
SH1  Short  [net_tie_coppertrace]
TP2  RED  [KEYSTONE_5000]
TP3  RED  [KEYSTONE_5000]
TP5  RED  [KEYSTONE_5000]
TP6  TP_SMD  [TP127D033]
TP10  TP_SMD  [TP127D033]
TP20  TP_SMD  [TP127D033]
TP25  TP_SMD  [TP127D033]
TP26  RED  [KEYSTONE_5000]
U1  CY8C6247BZI-D54  [BGA124C65P13X13_900X900X100]  (sections A,B)
U7  SIP32401ADNP  [TDFN50P160X120X60-5M]
U21  LMV321ILT  [SOT95P280X145-5M]
U25  INA216A3RSW  [QFN40P140X180X55-10M]

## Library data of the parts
ACC1 = PCB: ASSY, PCBA, CY8CKIT-062-WiFi-BT PSoC 6  WiFi-BT Pioneer Kit; Dist_Part_Number: -NA-; Distributor: -NA-; Mfr_Name: Cypress Approved CM; Mfr_Part#: -NA-; Mfr_Part_Number: -NA-
ACC2 = PCB: PCB, BARE, CY8CKIT-062-WiFi-BT PSoC 6  WiFi-BT Pioneer Kit; Dist_Part_Number: -NA-; Distributor: -NA-; Mfr_Name: Cypress Approved CM; Mfr_Part#: -NA-; Mfr_Part_Number: -NA-; Sub_Allowed: NO
ACC3 = PCB: DRW, FABRICATION DRAWING, CY8CKIT-062-WiFi-BT PSoC 6  WiFi-BT Pioneer Kit; Dist_Part_Number: -NA-; Distributor: -NA-; Mfr_Name: -NA-; Mfr_Part#: -NA-; Mfr_Part_Number: -NA-; Sub_Allowed: NO
ACC4 = PCB: DRW, ASSEMBLY DRAWING, CY8CKIT-062-WiFi-BT PSoC 6  WiFi-BT Pioneer Kit; Dist_Part_Number: -NA-; Distributor: -NA-; Mfr_Name: -NA-; Mfr_Part#: -NA-; Mfr_Part_Number: -NA-
ACC5 = PCB: DRW, SCHEMATIC DRAWING, CY8CKIT-062-WiFi-BT PSoC 6  WiFi-BT Pioneer Kit; Dist_Part_Number: -NA-; Distributor: -NA-; Mfr_Name: -NA-; Mfr_Part#: -NA-; Mfr_Part_Number: -NA-
C9 C67 C88 = CAPACITOR_NON-POL: CAP, CER, 1UF, 10%, 25V, X5R, 0402; Cy_Part#: 510-60560-01; Mfr_Name: Murata Electronics; Mfr_Part#: GRM155R61E105KA12D; Sub_Asm: Batt; Tolerance: 10%; VOLTAGE: 25V
C14 = CAPACITOR_NON-POL: CAP, CER, 0.1UF, 10%, X5R, 50V, 0402; Asm_Instruction: No Load; Cy_Part#: 510-60330-01; Mfr_Name: Taiyo Yuden; Mfr_Part#: UMK105BJ104KV-F; Sub_Asm: Batt; Tolerance: 10%; VOLTAGE: 50V
C39 C41 C45 C47 = CAPACITOR_NON-POL: CAP, CER, 4.7uF, 10%, 16V, X5R, 0603; Cy_Part#: 510-60058-01; Mfr_Name: Murata Electronic; Mfr_Part#: GRM188R61C475KAAJD; Mfr_Part_Number: GRM188R61C475KAAJD; Sub_Asm: Buck; Tolerance: 10%; VOLTAGE: 16V
C43 C46 C131 = CAPACITOR_NON-POL: CAP, CER, 0.1UF, 10%, X5R, 50V, 0402; Cy_Part#: 510-60330-01; Mfr_Name: Murata Electronics; Mfr_Part#: GRM155R61H104KE14D; Sub_Asm: Buck; Tolerance: 10%; VOLTAGE: 50V
C44 = CAPACITOR_NON-POL: CAP, CER, 0.1UF, 10%, X5R, 50V, 0402; Asm_Instruction: No Load; Cy_Part#: 510-60330-01; Mfr_Name: Taiyo Yuden; Mfr_Part#: UMK105BJ104KV-F; Sub_Asm: Buck; Tolerance: 10%; VOLTAGE: 50V
C52 = CAPACITOR_NON-POL: CAP, CER, 22UF, 10%, X5R, 25V, 1206; Cy_part#: 510-60493-01; Mfr_Name: Murata Electronics; Mfr_Part#: GRM31CR61E226KE15L; Sub_Asm: Batt; VOLTAGE: 25V
C63 = CAPACITOR_NON-POL: CAP, CER, 4.7uF, 10%, 25V, X5R, 0603; Cy_Part#: 510-60058-01; Mfr_Name: Murata Electronic; Mfr_Part#: GRM188R61C475KAAJD; Mfr_Part_Number: GRM188R61C475KAAJD; Sub_Asm: Batt; Tolerance: 10%; VOLTAGE: 16V
C64 = CAPACITOR_NON-POL: CAP, CER, 0.1UF, 10%, X5R, 50V, 0402; Cy_Part#: 510-60330-01; Mfr_Name: Murata Electronics; Mfr_Part#: GRM155R61H104KE14D; Sub_Asm: Batt; Tolerance: 10%; VOLTAGE: 50V
C73 = CAPACITOR_NON-POL: CAP CER 2.2UF 10V X5R 0402; Cy_Part#: 510-60376-01; Mfr_Name: Murata Electronics; Mfr_Part#: GRM155R61A225ME95D; VOLTAGE: 10V
C87 = CAPACITOR_NON-POL: CAP, CER, 10UF, 20%, 10V, X5R, 0402; Cy_Part#: 510-60337-01; Mfr_Name: Murata Electronics; Mfr_Part#: GRM155R60J106ME15D; Sub_Asm: Batt; VOLTAGE: 10V
J15 = CONN_FLEX_2: CONN HEADER PH R/A 2POS 2MM; Asm_Instruction: No Load; HARD_LOCATION: YES; Mfr_Name: JST Sales America Inc.; Mfr_Part#: S2B-PH-K-S(LF)(SN); Sub_Asm: Power In
L8 = INDUCTOR: IND, 1.5UH, 5.2A, 20% SMD; Mfr_Name: Pulse Electronics Corporation; Mfr_Part#: PA4332.152NLT; Sub_Asm: Batt; Tolerance: 20%
LED4 = LED_0: LED, 585nm, YELLOW, CLEAR, 0805, 12mcd, SMD; Cy_part#: 534-60076-01; HARD_LOCATION: YES; Mfr_Name: Chicago Miniature Lighting, LLC; Mfr_Part#: CMD17-21VYC/TR8; Sub_Asm: Buck
LED6 = LED_0: LED, HI EFF, RED, CLEAR, 0805, SMD; Cy_part#: 534-60064-01; HARD_LOCATION: YES; Mfr_Name: Chicago Miniature Lighting, LLC; Mfr_Part#: CMD17-21VRC/TR8; Sub_Asm: Batt
R1 R4-R6 R104 = RESISTOR: RES, 10K OHM, 5%, 1/10W, 0402, SMD; Asm_Instruction: No Load; Mfr_Name: Panasonic; Mfr_Part#: ERJ-2GEJ103X; TOLERANCE: 5%
R2 R9-R11 R95 R98 R100 = RESISTOR: RES, 10K OHM, 5%, 1/10W, 0402, SMD; Mfr_Name: Panasonic; Mfr_Part#: ERJ-2GEJ103X; Sub_Asm: Batt; Tolerance: 5%
R41 = RESISTOR: RES, 158K OHM, 1%, 100PPM, 1/16W, 0402; Mfr_Name: Yageo; Mfr_Part#: RC0402FR-07158KL; Sub_Asm: Regulator; Tolerance: 1%
R42 R123 = RESISTOR: RES, 49.9K OHM, 1%, 100PPM, 1/10W, 0402, SMD; Cy_part#: 500-60149-01; Mfr_Name: Panasonic; Mfr_Part#: ERJ-2RKF4992X; Mfr_Part_Number: ERJ-2RKF4992X; Sub_Asm: KitProg; Tolerance: 1%
R46 = RESISTOR: RES, 160K OHM, 1%, 1/10W, 0402, SMD; Mfr_Name: Yageo; Mfr_Part#: RC0402FR-07160KL; Tolerance: 1%
R48 = RESISTOR: RES, 49.9K OHM, 1%, 100PPM, 1/10W, 0402, SMD; Cy_part#: 500-60149-01; Mfr_Name: Panasonic; Mfr_Part#: ERJ-2RKF4992X; Sub_Asm: Buck; Tolerance: 1%
R49 = RESISTOR: RES, 10K OHM, 5%, 1/10W, 0402, SMD; Mfr_Name: Panasonic; Mfr_Part#: ERJ-2GEJ103X; Sub_Asm: Buck; Tolerance: 5%
R50 = RESISTOR: RES, 62K OHM, 1%, 100PPM, 1/16W, 0402; Mfr_Name: Yageo; Mfr_Part#: RC0402FR-0762KL; Sub_Asm: Regulator; Tolerance: 1%
R51 = RESISTOR: RES SMD 22.6K OHM 1% 1/16W 0402; Mfr_Name: Yageo; Mfr_Part#: RC0402FR-0722K6L; Sub_Asm: Buck; Tolerance: 1%
R57 = RESISTOR: RES, 390 OHM, 5%, 1/10W, 0402, SMD; Mfr_Name: Panasonic; Mfr_Part#: ERJ-2GEJ391X; Sub_Asm: Buck; Tolerance: 5%
R92 = RESISTOR: RES, 26.7K OHM, 1%, 1/10W, 0402, SMD; Mfr_Name: Panasonic; Mfr_Part#: ERJ-2RKF2672X; Sub_Asm: Batt; Tolerance: 1%
R94 = RESISTOR: RES, 100K OHM, 5%, 200PPM, 1/10W, 0402; Asm_Instruction: No Load; Cy_part#: 500-60075-01; Mfr_Name: Panasonic; Mfr_Part#: ERJ-2GEJ104X; Sub_Asm: Batt; Tolerance: 5%
R102 = RESISTOR: RES, 750 OHM, 5%, 1/10W, 0402, SMD; Mfr_Name: Yageo; Mfr_Part#: RC0402JR-07750RL; Sub_Asm: Batt; Tolerance: 5%
R105 = RESISTOR: RES, 400 OHM, 1%, 1/10W, 0402, SMD; Cy_part#: 500-60075-01; Mfr_Name: Panasonic; Mfr_Part#: ERJ-2RKF4020X; Sub_Asm: Batt; Tolerance: 1%
R155 R157 = RESISTOR: RES, 4.7K OHM, 5%, 100PPM, 1/16W, 0402; Cy_part#: 500-60095-01; Mfr_Name: Yageo; Mfr_Part#: RC0402JR-074K7L; Sub_Asm: Buck; Tolerance: 5%
SW5 = SW_SP3T: Slide Switch SP3T Surface Moun; HARD_LOCATION: YES; Mfr_Name: Copal Electronics Inc.; Sub_Asm: Buck
TP7 = TEST_POINT: TEST POINT PC MINI .040"D RED; Asm_Instruction: No Load; Cy_Part_Number: 711-60001-01; Cy_part#: 711-60001-01; DEVICE: TP-43R_R; Dist_Part_Number: 36-5000-ND; Distributor: Digikey; Mfr_Name: Keystone Electronics; Mfr_Part#: 5000; ROHS: YES; Sub_Asm: Batt
TP9 = TEST_POINT: TEST POINT PC MINI .040"D RED; Asm_Instruction: No Load; Cy_Part_Number: 711-60001-01; Cy_part#: 711-60001-01; DEVICE: TP-43R_R; Dist_Part_Number: 36-5000-ND; Distributor: Digikey; Mfr_Name: Keystone Electronics; Mfr_Part#: 5000; ROHS: YES; Sub_Asm: Buck
TP21 = TEST_POINT: TEST POINT PC MINI .040"D RED; Asm_Instruction: No Load; Cy_Part_Number: 711-60001-01; Cy_part#: 711-60001-01; DEVICE: TP-43R_R; Dist_Part_Number: 36-5000-ND; Distributor: Digikey; Mfr_Name: Keystone Electronics; Mfr_Part#: 5000; ROHS: YES; Sub_Asm: Power In
U8 = SiP32408_0: IC SW W/CTRL SLEW RATE 4TDFN; Mfr_Name: Vishay Siliconix; Mfr_Part#: SIP32408DNP-T1-GE4
U9 U10 = AP7365-WG-7: IC REG LIN POS ADJ 600MA SOT25-5; Mfr_Name: Diodes Incorporated
U19 = BQ24266RGER_4: IC BATT CHARGER LI-ION 24VQFN; Mfr_Name: Texas Instruments; Sub_Asm: Batt
U27 = ISL95810UIU8Z-T: IC, POT, DGTL, 50K OHM, 8-MSOP; Cy_part#: 450-60191-01; Mfr_Name: Intersil; Sub_Asm: Buck
C30 C32 C40 C97 C107 C113 C118 C122 C126 C127 C130 C132 C147 = CAPACITOR_NON-POL: CAP, CER, 1UF, 10%, 25V, X5R, 0402; Cy_Part#: 510-60560-01; Mfr_Name: Murata Electronics; Mfr_Part#: GRM155R61E105KA12D; Sub_Asm: KitProg; Tolerance: 10%; VOLTAGE: 25V
C16 C34 C90 C91 C106 C115 C116 C123 C125 C128 C129 = CAPACITOR_NON-POL: CAP, CER, 0.1UF, 10%, X5R, 50V, 0402; Cy_Part#: 510-60330-01; Mfr_Name: Murata Electronics; Mfr_Part#: GRM155R61H104KE14D; Sub_Asm: KitProg; Tolerance: 10%; VOLTAGE: 50V
LED1 = LED_0: LED, HI EFF, RED, CLEAR, 0805, SMD; Cy_part#: 534-60064-01; HARD_LOCATION: YES; Mfr_Name: Chicago Miniature Lighting, LLC; Mfr_Part#: CMD17-21VRC/TR8; Sub_Asm: KitProg
LED2 = LED_0: LED, 585nm, YELLOW, CLEAR, 0805, 12mcd, SMD; Cy_part#: 534-60076-01; HARD_LOCATION: YES; Mfr_Name: Chicago Miniature Lighting, LLC; Mfr_Part#: CMD17-21VYC/TR8; Sub_Asm: KitProg
LED3 = LED_0: LED, 570nm, GREEN, 10mcd, 0805, SMD; Cy_part#: 534-60024-01; HARD_LOCATION: YES; Mfr_Name: Chicago Miniature Lighting, LLC; Mfr_Part#: CMD17-21VGC/TR8; Sub_Asm: KitProg
R34 R35 = RESISTOR: RES, 22 OHM, 1%, 100PPM, 1/16W, 0402; Cy_part#: 500-60085-01; Mfr_Name: Yageo; Mfr_Part#: RC0402FR-0722RL; Mfr_Part_Number: RC0402FR-0722RL; Sub_Asm: KitProg; Tolerance: 1%
R40 R43 = RESISTOR: RES, 4.7K OHM, 5%, 100PPM, 1/16W, 0402; Cy_part#: 500-60095-01; Mfr_Name: Yageo; Mfr_Part#: RC0402JR-074K7L; Sub_Asm: KitProg; Tolerance: 5%
R54-R56 = RESISTOR: RES, 750 OHM, 5%, 1/10W, 0402, SMD; Mfr_Name: Yageo; Mfr_Part#: RC0402JR-07750RL; Sub_Asm: KitProg; Tolerance: 5%
R106 R118 = RESISTOR: RES, 120K OHM, 5%, 1/10W, 0402, SMD; Mfr_Name: Panasonic; Mfr_Part#: ERJ-2GEJ124X; Sub_Asm: KitProg; Tolerance: 5%
R15 R26 R29 R30 R124 = RESISTOR: RES SMD 0.0OHM JUMPER 1/10W 0603; Asm_Instruction: No Load; Cy_part#: 500-60108-01; Mfr_Name: Rohm Semiconductor; Mfr_Part#: MCR03EZPJ000; Sub_Asm: KitProg
R125 = RESISTOR: RES, 75K OHM, 5%, 1/10W, 0402, SMD; Mfr_Name: Panasonic; Mfr_Part#: ERJ-2GEJ753X; Sub_Asm: KitProg; Tolerance: 5%
R141 R150 R156 R159 = RESISTOR: RES SMD 0.0OHM JUMPER 1/10W 0603; Cy_part#: 500-60108-01; Mfr_Name: Rohm Semiconductor; Mfr_Part#: MCR03EZPJ000; Sub_Asm: KitProg
SW3 SW4 = SW_PUSH_NO_4-PIN: SW, TACTILE SWITCH, 4.2x3.2x2.5MM, 260GF; Cy_part#: 770-60033-01; HARD_LOCATION: YES; Mfr_Name: ALPS ELECTRIC CO.,LTD; Sub_Asm: KitProg
U2 = CY8C38***-QFN68_1: IC, CYPRESS, PSoC 5LP, RAM 64KB, 32 Bit MCU, 68PIN, QFN; HARD_LOCATION: YES; Mfr_Name: Cypress Semiconductor; Sub_Asm: KitProg
U7 U23 = SIP32402ADNP_1: IC SW W/CTRL SLEW RATE 4TDFN; Mfr_Name: Vishay Siliconix; Mfr_Part#: SIP32401ADNP-T1GE4; Sub_Asm: KitProg
C55 C56 = CAP_NP: CAP, CER, 1UF, 10%, 25V, X5R, 0402; Cy_part#: 510-60560-01; Dist_Part_Number: 490-10694-1-ND; Distributor: Digikey; Mfr_Name: Murata Electronics; Mfr_Part#: GRM155R61E105KA12D; Tolerance: 10%; VOLTAGE: 25V
C80 C84 C124 = CAPACITOR_NON-POL: CAP, CER, 0.1UF, 10%, X5R, 50V, 0402; Asm_Instruction: No Load; Cy_Part#: 510-60330-01; Mfr_Name: Taiyo Yuden; Mfr_Part#: UMK105BJ104KV-F; Sub_Asm: KitProg; Tolerance: 10%; VOLTAGE: 50V
D10 = DIODE_ZENER_2: DIODE, ZENER, 3.9V, 500MW, SOD123; Cy_part#: 530-60069-01; Mfr_Name: Diodes Inc; Sub_Asm: KitProg
J6 = CONN_7: CONN, FEMALE, 2.54mm, 16POS, DL, GOLD, TH; Asm_Instruction: No Load; CLASS: IO; HARD_LOCATION: YES; Mfr_Name: Sullins Connector Solutions; Mfr_Part#: PPPC082LFBN-RC; Pitch: 100 mil; Sub_Asm: KitProg
J7 = RECPT_4X2_100MIL_5: CONN, HEADER, FEMALE, 2.54mm, DOUBLE, GOLD, 10POS, TH; Asm_Instruction: No Load; Cy_part#: 720-60283-01; HARD_LOCATION: YES; Mfr_Name: Sullins Connector Solutions; Mfr_Part#: PPPC052LFBN-RC; Sub_Asm: KitProg
J11 = RECPT_4X2_100MIL_2: CONN, BOX, HEADER, 0.050", 10POS; Cy_part#: 720-60230-01; HARD_LOCATION: YES; Mfr_Name: CNC Tech; Mfr_Part#: 3220-10-0100-00; Sub_Asm: KitProg
J12 = 20-pin_connector: BOX HEADER, 0.050 20 POS; HARD_LOCATION: YES; Mfr_Name: CNC Tech; Mfr_Part#: 3220-20-0100-00
Q2 = P_DGS_5: MOSFET, P-CH, 20V, 3.5A, SOT23; Cy_part#: 532-60017-01; Mfr_Name: NXP Semiconductors; Sub_Asm: KitProg
Q3 = P_DGS_4: FET, MOSFET, P-CHNL, 30V, 3.8A, 1.08W, SOT-23; Cy_part#: 532-60008-01; Mfr_Name: Diodes Inc; Sub_Asm: KitProg
Q4 = P_DGS_5: MOSFET, P-CH, 30V, 2.2A, SOT23; Cy_part#: 532-60016-01; Mfr_Name: ON Semiconductor; Sub_Asm: KitProg
R33 R136 = RESISTOR: RES, 30K OHM, 1/10W, 5%, 0402, SMD; Cy_part#: 500-60446-01; Mfr_Name: Panasonic - ECG; Mfr_Part#: ERJ-2GEJ303X; Mfr_Part_Number: ERJ-2GEJ303X; Sub_Asm: KitProg; Tolerance: 5%
R37 R130 = RESISTOR: RES, 15K OHM, 1/10W, 5%, 0402, SMD; Cy_part#: 500-60445-01; Mfr_Name: Panasonic - ECG; Mfr_Part#: ERJ-2GEJ153X; Mfr_Part_Number: ERJ-2GEJ153X; Sub_Asm: KitProg; Tolerance: 5%
R77 R81 R85 R88 R93 R138 R143 R182 R183 R190-R192 R194 = RESISTOR: RES SMD 0.0OHM JUMPER 1/10W 0603; Cy_part#: 500-60108-01; Mfr_Name: Rohm Semiconductor; Mfr_Part#: MCR03EZPJ000
R119 = RESISTOR: RES, 49.9K OHM, 1%, 100PPM, 1/10W, 0402, SMD; Asm_Instruction: No Load; Cy_part#: 500-60149-01; Mfr_Name: Panasonic; Mfr_Part#: ERJ-2RKF4992X; Mfr_Part_Number: ERJ-2RKF4992X; Sub_Asm: KitProg; Tolerance: 1%
R193 = RESISTOR: RES, 15K OHM, 1/10W, 5%, 0402, SMD; Cy_part#: 500-60445-01; Mfr_Name: Panasonic - ECG; Mfr_Part#: ERJ-2GEJ153X; Sub_Asm: KitProg; Tolerance: 5%
R195 R204 = RESISTOR: RES, 10K OHM, 5%, 1/10W, 0402, SMD; Mfr_Name: Panasonic; Mfr_Part#: ERJ-2GEJ103X; Sub_Asm: KitProg; Tolerance: 5%
R196 = 330_ohm_5%_0805_0: RES SMD 0.0OHM JUMPER 1/10W 0603; Asm_Instruction: No Load; Cy_part#: 500-60108-01; Mfr_Name: Rohm Semiconductor; Mfr_Part#: MCR03EZPJ000; Sub_Asm: KitProg
TVS4 = TVS_5V_SOD-323_0: DIO, TVS, UNIDIR, 158W, 3.3V, SOD-523; Mfr_Name: Micro Commercial Co; Sub_Asm: KitProg
U17 = FXMA108_0: TRANSLATOR 8BIT DUAL 3ST 20DQFN; Mfr_Name: Fairchild Semiconductor
U26 = SIP32402ADNP_1: IC SW W/CTRL SLEW RATE 4TDFN; Mfr_Name: Vishay Siliconix; Mfr_Part#: SIP32402ADNP-T1GE4; Sub_Asm: KitProg
C8 = CAPACITOR_NON-POL: CAP, CER, 1UF, 10%, 25V, X5R, 0402; Asm_Instruction: No Load; Cy_Part#: 510-60560-01; Mfr_Name: Murata Electronics; Mfr_Part#: GRM155R61E105KA12D; Tolerance: 10%; VOLTAGE: 25V
C10 C15 C18 C20 C22 C25 C28 C35 C38 C68 C69 C72 C79 C83 C102 C104 C105 C117 C119 = CAPACITOR_NON-POL: CAP, CER, 0.1UF, 10%, X5R, 50V, 0402; Cy_Part#: 510-60330-01; Mfr_Name: Murata Electronics; Mfr_Part#: GRM155R61H104KE14D; Tolerance: 10%; VOLTAGE: 50V
C19 C21 C26 C36 C37 C42 C70 C71 C77 C78 C93 C100 C101 C114 C144 = CAPACITOR_NON-POL: CAP, CER, 1UF, 10%, 25V, X5R, 0402; Cy_Part#: 510-60560-01; Mfr_Name: Murata Electronics; Mfr_Part#: GRM155R61E105KA12D; Tolerance: 10%; VOLTAGE: 25V
D1 D2 = DIO_STKY_PMEG3020_0: DIODE SCHOTTKY 20V 500mA 0603; Cy_part#: 530-60136-01; Mfr_Name: Rohm Semiconductor; Sub_Asm: Power In
LED7 = LED_0: LED, 570nm, GREEN, 10mcd, 0805, SMD; Cy_part#: 534-60024-01; HARD_LOCATION: YES; Mfr_Name: Chicago Miniature Lighting, LLC; Mfr_Part#: CMD17-21VGC/TR8
R3 R14 = RESISTOR: RES, 75K OHM, 5%, 1/10W, 0402, SMD; Mfr_Name: Panasonic; Mfr_Part#: ERJ-2GEJ753X
R7 R16 = RESISTOR: RES, 120K OHM, 5%, 1/10W, 0402, SMD; Mfr_Name: Panasonic; Mfr_Part#: ERJ-2GEJ124X
R75 = RESISTOR: RES, 750 OHM, 5%, 1/10W, 0402, SMD; Mfr_Name: Yageo; Mfr_Part#: RC0402JR-07750RL
TP6 TP10 TP20 TP25 TP29 TP30 TP32 TP36 TP38 TP39 = TEST_POINT: TESTPOINT, SMD, 40MILS, ROUND; Asm_Instruction: No Load; Mfr_Name: -NA-; Mfr_Part#: -NA-
U3 = CYPD3125-40LQXIES_3: HARD_LOCATION: YES; Mfr_Name: Cypress Semiconductor
C49 = CAPACITOR_NON-POL: CAP, CER, 10uF, 10%, 25V, X5R, 0805; Cy_Part#: 510-60052-01; Mfr_Name: Murata Electronics; Mfr_Part#: GRM21BR61E106KA73L; Sub_Asm: Power In; Tolerance: 10%; VOLTAGE: 25V
C74 C145 = CAPACITOR_NON-POL: CAP, CER, 0.01uF, 10%, X7R, 50V, 0402; Cy_part#: 510-60089-01; Mfr_Name: Murata Electronics; Mfr_Part#: GRM155R71H103KA88D; Mfr_Part_Number: GRM155R71H103KA88D; Tolerance: 10%; VOLTAGE: 50V
C120 = CAPACITOR_NON-POL: CAP, CER, 22UF, 20%, X5R, 25V, 0805; Cy_part#: 510-60564-01; Mfr_Name: Murata Electronics; Mfr_Part#: GRM21BR61E226ME44L; Tolerance: 20%; VOLTAGE: 25V
C146 = CAPACITOR_NON-POL: CAP, CER, 1UF, 10%, 25V, X5R, 0402; Asm_Instruction: No Load; Mfr_Name: Murata Electronics; Mfr_Part#: GRM155R61E105KA12D; Tolerance: 10%; VOLTAGE: 25V
D8 D9 = DIO_STKY_PMEG3020_0: DIODE SCHOTTKY 30V 2A SOD128; Cy_part#: 530-60131-01; Mfr_Name: NXP Semiconductors; Mfr_Part#: PMEG3020BEP,115; Sub_Asm: Power In
J16 = Terminal_Block: CONN, TERM, BLOCK, 2.54MM, 2POS, PCB; Asm_Instruction: No Load; Cy_part#: 720-60267-01; HARD_LOCATION: YES; Mfr_Name: On Shore Technology Inc.
Q1 = MOSFET_N_GDS_10: MOSFET 2N-CH 30V 11A 8SOIC; Mfr_Name: Alpha & Omega Semiconductor Inc.
R84 R184 = RESISTOR: RES, 10K OHM, 5%, 1/10W, 0402, SMD; Mfr_Name: Panasonic; Mfr_Part#: ERJ-2GEJ103X; TOLERANCE: 5%
R87 = RESISTOR: RES, 150 OHM, 1%, 1/10W, 0402, SMD; Cy_part#: 500-60044-01; Mfr_Name: Panasonic; Mfr_Part#: ERJ-2RKF1500X; TOLERANCE: 1%
R127 = 100-16W-1%-2512: RES SMD 200 OHM 1% 3W 2512; Mfr_Name: TE Connectivity; Mfr_Part#: 3522200RFT; Wattage: 3W
R137 R144 = R: RES SMD 10M OHM 5% 1/16W 0402; Mfr_Name: Rohm Semiconductor; Mfr_Part#: TRR01MZPJ106; TOLERANCE: 5%
R139 R151 = RESISTOR: RES SMD 0.0OHM JUMPER 1/10W 0603; Asm_Instruction: No Load; Cy_part#: 500-60108-01; Mfr_Name: Rohm Semiconductor; Mfr_Part#: MCR03EZPJ000
R129 R140 = RESISTOR: RES, 0 OHM, 1/10W, 0402, SMD; Mfr_Name: Panasonic; Mfr_Part#: ERJ-2GE0R00X
R154 = RESISTOR: RES SMD 0.01 OHM 1% 3W 2512; Mfr_Name: Bourns Inc; Mfr_Part#: CRA2512-FZ-R010ELF; TOLERANCE: 1%; Wattage: 3W
R185 = RESISTOR: RES, 4.7K OHM, 5%, 100PPM, 1/16W, 0402; Cy_part#: 500-60095-01; Mfr_Name: Yageo; Mfr_Part#: RC0402JR-074K7L; Tolerance: 5%
U13 = BTS4175SGA: IC SWITCH PWR HISIDE 8DSO; Mfr_Name: Infineon Technologies
U31 = SiP32429_1: IC LOAD SW LVL SHIFT 10DFN; Mfr_Name: Vishay; Mfr_Part#: SiP32429DN-T1-GE4
C23 C98 = CAPACITOR_NON-POL: CAP, CER, 4.7uF, 20%, 6.3V, X5R, 0402; Cy_Part#: 510-60058-01; Mfr_Name: Murata Electronic; Mfr_Part#: GRM188R61C475KAAJD; Mfr_Part_Number: GRM188R61C475KAAJD; Tolerance: 10%; VOLTAGE: 16V
C24 = CAPACITOR_NON-POL: CAP, CER, 10UF, 20%, 10V, X5R, 0402; Cy_Part#: 510-60337-01; Mfr_Name: Murata Electronics; Mfr_Part#: GRM155R60J106ME15D; VOLTAGE: 10V
J8 = 2_PIN_Header: HARD_LOCATION: YES; Mfr_Name: Harwin Inc.; Mfr_Part#: M20-9960245
L4-L6 = INDUCTOR_FERRITE: FERRITE BEAD 1 KOHM 0805; CLASS: DISCRETE; Mfr_Name: Murata Electronics; Mfr_Part#: BLM21AG102SN1D; PART_TYPE: FERRITE; ROHS: YES
L9 = INDUCTOR: FIXED IND 2.2UH 1.2A 138 MOHM; Mfr_Name: Murata Electronics; Mfr_Part#: LQM2MPN2R2MG0L
R148 = 330_ohm_5%_0805_0: RES SMD 0.2 OHM 1% 1/6W 0402; Mfr_Name: Panasonic; Mfr_Part#: ERJ-2BSFR20X; Tolerance: 1%
SH1 = Short_2: Net short, Copper trace; Asm_Instruction: No Load; Mfr_Name: -NA-; Mfr_Part#: -NA-
TP2 TP3 TP5 TP26 = TEST_POINT: TEST POINT PC MINI .040"D RED; Asm_Instruction: No Load; CLASS: DISCRETE; Cy_part#: 711-60001-01; Mfr_Name: Keystone Electronics; Mfr_Part#: 5000; ROHS: YES
U1 = PSoC6_BLE_Hetero_0: MCU, PSoC 6, Performance, 1024KB, 124B-GA, Dual Core,150MHz; HARD_LOCATION: YES; Mfr_Name: Cypress
U21 = OP-07_4: IC OPAMP GP 1.3MHZ RRO SOT23-5; Mfr_Name: STMicroelectronics
U25 = INA216A3RSW_2: IC CURRENT SHUNT MONITOR 10UQFN; Mfr_Name: Texas Instruments

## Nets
5V_OUT: D8.A(ANODE) ; also on sheet 16
GND: C8.2 C10.2 C14.2 C15.2 C16.1 C18.2 C19.2 C20.2 C21.2 C22.2 C23.2 C24.2 C25.2 C26.2 C28.2 C30.1 C32.2 C34.2 C35.2 C36.2 C37.2 C38.2 C39.2 C40.2 C41.2 C42.2 C43.2 C44.1 C45.2 C46.2 C47.2 C49.2 C52.2 C55.2 C56.1 C63.2 C64.2 C67.2 C68.2 C69.2 C70.2 C71.2 C72.2 C73.2 C74.1 C77.2 C78.1 C79.2 C80.1 C83.2 C87.2 C88.2 C90.1 C91.2 C93.2 C97.2 C98.2 C100.2 C101.2 C102.1 C104.2 C105.2 C106.2 C107.2 C113.2 C114.2 C115.2 C116.2 C117.2 C118.2 C119.1 C120.2 C122.2 C123.2 C124.2 C125.2 C126.2 C127.2 C128.2 C129.2 C130.2 C131.2 C132.2 C144.1 C145.1 C146.1 C147.2 D10.A(ANODE) J6.16 J7.4 J11.3 J11.5 J11.7 J11.9 J12.3 J12.5 J12.9 J12.15 J12.17 J12.19 J15.2 J16.1 LED1.K(CATHODE) LED2.K(CATHODE) LED3.K(CATHODE) LED4.K(CATHODE) Q3.1(G) R2.2 R3.1 R4.1 R9.2 R10.2 R14.1 R33.1 R42.1 R46.1 R48.2 R84.1 R87.2 R94.1 R98.1 R100.2 R105.2 R119.1 R125.1 R136.1 R140.1 R184.1 R185.1 R195.1 R204.1 SH1.1 SW3.3 SW3.4 SW4.3 SW4.4 SW5.2 TP20.1 TP30.1 TVS4.A U1.B12(VSS0) U1.C3(VSS1) U1.D4(VSS2) U1.D10(VSS3) U1.K4(VSS4) U1.K10(VSS5) U2.5(VSSB) U2.7(VBOOST) U2.8(VBAT) U2.9(VSSD) U2.25(VSSD) U2.43(VSSA) U2.45(VSSD) U2.58(VSSD) U2.63(P2[1]) U2.69(EPAD) U3.33(VSS) U3.41(EPAD) U7.2(GND) U7.H(PAD) U8.2(GND) U8.H(PAD) U9.2(GND) U10.2(GND) U17.10(GND) U19.20(AGND) U19.21(PGND) U19.22(PGND) U19.EPAD U21.2(COMP2) U23.2(GND) U23.H(PAD) U25.9(GND) U26.2(GND) U26.H(PAD) U27.4(GND) U27.5(RW) U27.6(RL) U31.6(GND) U31.EPAD ; also on sheet 10 11 12 13 16
VBAT: C88.1 J15.1 U19.8(BAT) U19.9(BAT)
VBAT_PP: C52.1 C87.1 D1.A(ANODE) L8.2 U19.6(SYS) U19.7(SYS)
VBUS_DISCHARGE: R127.2 U3.32(VBUS_DISCHARGE)
VBUS_P_CTRL0: R143.1 R144.2 U3.2(VBUS_P_CTRL0)
VBUS_P_CTRL1: R137.1 R138.1 U3.1(VBUS_P_CTRL1)
VBUS_TC: C74.2 C78.2 C102.2 Q1.7(D2) Q1.8(D2) R7.1 R26.1 R118.1 R127.1 U13.5(VS_1) U13.6(VS_2) U13.7(VS_3) U13.8(VS_4) ; also on sheet 16
VBUS_TC_MON: C10.1 R3.2 R7.2 U3.24(P2.5)
VCC_3V3: C16.2 C41.1 R15.1 R41.2 R57.1 TP9.1 U7.3(IN) U9.5(OUT) ; also on sheet 11 12 13 16
VCC_5V: C39.1 C43.1 C46.1 C47.1 C63.1 C64.1 C90.2 C131.1 D2.A(ANODE) R1.2 R5.2 R6.2 R92.2 R124.1 U9.1(IN) U10.1(IN) U19.18(IN) U19.19(IN) U21.5(COMP1) U23.3(IN) U27.8(VCC) ; also on sheet 10 12 16
VCC_VAR: C45.1 R49.1 R50.2 U8.1(IN) U10.5(OUT)
VCCD: C93.1 R129.2 TP6.1 U1.A2(VCCD)
VDD_NS: C18.1 C24.1 L4.2 TP3.1 U1.J1(VDD_NS)
VDDA: C35.1 C36.1 C37.1 C38.1 L6.2 TP26.1 U1.A12(VDDA) U1.A13(VDDIOA)
VDDD: C20.1 C26.1 C100.1 C101.1 C104.1 C105.1 C114.1 C117.1 L5.2 TP2.1 U1.A1(VDDD) U1.C4(VDDIO0) U1.K12(VDDIO1) U1.L4(VDDIOR) ; also on sheet 10 12
VDDUSB: C21.1 C22.1 R15.2 TP10.1 U1.M1(VDDUSB) U7.1(OUT)
VIN: C144.2 C145.2 R16.1 U31.1(VIN) U31.2(VIN) ; also on sheet 11 16
VIN_MON: C15.1 R14.2 R16.2 U3.25(P2.6)
CC1: U3.5(CC1) ; also on sheet 16
CC2: U3.3(CC2) ; also on sheet 16
CCG_12V_EN: R184.2 U3.35(P3.3) U31.4(EN)
CCG_LED: LED7.K(CATHODE) U3.34(P3.2)
CCG_O_EN: R84.2 U3.38(P3.6) U13.2(IN)
CCG_SWDCLK: TP36.1 U3.16(P2.1)
CCG_SWDIO: TP38.1 U3.15(P2.0)
CCG_VBUS_OUT: D8.K(CATHODE) D9.K(CATHODE) R154.1 U3.40(VBUS_P)
CCG_VCCD: C71.1 C72.1 U3.19(VCCD)
CCG_VDD: C68.1 C69.1 C70.1 U3.17(VDDD) U3.18(VDDIO)
CCG_VSYS: C8.1 C77.1 C79.1 D1.K(CATHODE) D2.K(CATHODE) R75.1 TP29.1 U3.20(VSYS)
CCG_XRES_L: C83.1 TP32.1 U3.26(XRES)
CE_L: C14.1 R4.2 R11.2 U3.10(P1.3) U19.4(~{CE})
CHG_L: R102.1 U19.13(~{CHG})
DIGPOT_SCL: R155.2 U2.68(P2[5]) U27.2(SCL)
DIGPOT_SDA: R157.2 U2.1(P2[6]) U27.3(SDA)
I2C_SCL: J6.6 R30.1 R40.1 R141.1 U2.38(P12[0])
I2C_SCL_EC: R30.2 U3.37(P3.5)
I2C_SDA: J6.10 R29.1 R43.1 R150.1 U2.39(P12[1])
I2C_SDA_EC: R29.2 U3.36(P3.4)
IN_N: C84.1 R106.1 U21.3(-IN)
IUSB1: R1.1 R2.1 U3.7(P1.0) U19.17(IUSB1)
IUSB2: R6.1 R9.1 U3.8(P1.1) U19.16(IUSB2)
IUSB3: R5.1 R10.1 U3.9(P1.2) U19.14(IUSB3)
KP2_SWCLK: R183.2 U2.47(P12[3])
KP2_SWD_RST_L: R182.2 U2.3(P12[4])
KP2_SWDIO: R194.2 U2.46(P12[2])
KP_PMIC_EN: U2.2(P2[7]) ; also on sheet 10
KP_PMIC_EN_OUT: U27.1(~{WP}) ; also on sheet 10
P5_0: R159.2 ; also on sheet 9 11
P5_1: R156.2 ; also on sheet 9 11
P5_2: R93.1 R204.2 ; also on sheet 9 11
P5_3: R88.1 ; also on sheet 9 11
P5LP0_1: J6.4 U2.49(P0[1])
P5LP0_2: J7.1 U2.50(P0[2])
P5LP0_3: J7.3 U2.51(P0[3])
P5LP0_5: TP25.1 U2.30(P3[1]) U2.54(P0[5]) U25.10(OUT)
P5LP0_6: SH1.2 U2.37(P3[7]) U2.55(P0[6])
P5LP0_7: J7.5 U2.56(P0[7])
P5LP1_2: SW3.1 SW3.2 U2.13(P1[2])
P5LP1_3: R56.1 U2.14(P1[3])
P5LP1_4: R54.1 U2.15(P1[4])
P5LP1_5: R55.1 U2.16(P1[5])
P5LP2_0: U2.62(P2[0])
P5LP2_2: U2.64(P2[2])
P5LP2_3: U2.65(P2[3])
P5LP2_4: U2.66(P2[4])
P5LP3_0: J6.8 U2.29(P3[0])
P5LP3_4: J6.11 U2.33(P3[4])
P5LP3_5: J6.12 U2.34(P3[5])
P5LP3_6: J6.15 U2.36(P3[6])
P5LP15_0: SW4.1 SW4.2 U2.27(P15[0])
P5LP15_4: J7.9 U2.60(P15[4])
P5LP_SIO_VREF: R119.2 R123.1 U2.48(P0[0])
P5LP_SSEL_P12_4: U17.5(A3) ; also on sheet 9
P5LP_SWDCLK: J7.8 U2.12(P1[1])
P5LP_SWDIO: J7.10 U2.11(P1[0])
P5LP_USB_DM: R34.1 ; also on sheet 16
P5LP_USB_DP: R35.1 ; also on sheet 16
P5LP_VCCA: C40.1 U2.42(VCCA)
P5LP_VCCD: C30.2 C132.1 U2.26(VCCD) U2.57(VCCD)
P5LP_VDD: C32.1 C34.1 C56.2 C106.1 C107.1 C113.1 C115.1 C116.1 C118.1 C122.1 C123.1 C124.1 C125.1 C126.1 C127.1 C128.1 J6.1 J7.2 R37.1 R124.2 R155.1 R157.1 U2.17(VDDIO1) U2.24(VDDD) U2.35(VDDIO3) U2.44(VDDA) U2.52(VDDIO) U2.59(VDDD) U2.67(VDDIO2) U17.20(VCCB) U23.1(OUT) U26.4(EN) ; also on sheet 10
P5LP_XRES_L: J7.6 U2.10(~{XRES})
P6_0: R141.2 ; also on sheet 9 11
P6_1: R150.2 ; also on sheet 9 11
P6_4: J11.6 J12.6 ; also on sheet 9
P6_5: J11.8 J12.8 ; also on sheet 9
P6_6: R192.1 ; also on sheet 9
P6_7: R191.1 ; also on sheet 9
P6_VDD: C55.1 Q4.3(D) R40.2 R43.2 R104.1 R148.2 R196.2 TP21.1 U8.4(OUT) U17.1(VCCA) U25.2(IN+) U25.3(IN+) ; also on sheet 10 11 12 13
P12_0: R77.1 ; also on sheet 9 11
P12_1: R85.1 ; also on sheet 9 11
P12_2: R81.1 ; also on sheet 9 11
PMIC_EN: U9.3(EN) U10.3(EN) ; also on sheet 10
SPI_MISO: J6.9 U2.4(P12[5]) U17.17(B2)
SPI_MOSI: J6.3 U2.28(P15[1]) U17.19(B0)
SPI_SCLK: J6.5 U2.40(P15[2]) U17.18(B1)
SPI_SSEL: J6.7 U2.41(P15[3]) U17.16(B3)
SWD_RST_L: J11.10 J12.10 R182.1 R190.2 ; also on sheet 11
TCLK_SWCLK: J11.4 J12.4 R183.1 R191.2
TMS_SWDIO: J11.2 J12.2 R192.2 R194.1
TRACECLK: J12.12 ; also on sheet 9
TRACEDATA_0: J12.14 ; also on sheet 9
TRACEDATA_1: J12.16 ; also on sheet 9
TRACEDATA_2: J12.18 ; also on sheet 9
TRACEDATA_3: J12.20 ; also on sheet 9
TS: R94.2 R95.1 TP7.1 U19.5(TS)
UART_CTS: J6.2 U2.61(P15[5]) U17.14(B5)
UART_RTS: J7.7 U2.18(P1[6]) U17.15(B4)
UART_RX: J6.13 R156.1 U2.21(P12[7])
UART_TX: J6.14 R159.1 U2.20(P12[6])
USB_TC_PWR_SENSE: C119.2 C120.1 Q1.5(D1) Q1.6(D1) R154.2 U3.39(OC)
USB_V_SENSE: R33.2 R37.2 U2.19(P1[7])
VBACKUP: C19.1 C25.1 U1.D1(VBACKUP) ; also on sheet 10
VBUCK1: C98.1 R129.1 U1.K3(VBUCK1)
VDRV: C73.1 LED6.A(ANODE) R95.2 U19.3(DRV)
VREF: C42.1 U1.B13(VREF) ; also on sheet 11
VRF: C23.1 TP5.1 U1.K1(VRF)
VTARG: J8.2 L4.1 L5.1 L6.1 R151.2 U21.1(+IN)
VTARG_BUF: C80.2 C84.2 C129.1 R106.2 U7.4(EN) U21.4(OUT) U26.3(IN)
VTARG_IN: J12.11 J12.13 R11.1 ; also on sheet 16
VTARG_MEAS: R130.2 R136.2 U2.32(P3[3])
VTARG_MON: R123.2 R130.1 U26.1(OUT)
VTARG_REF: C147.1 J11.1 J12.1 Q3.3(D) R196.1 TVS4.K
XRES_L: R190.1 ; also on sheet 9 10
N17133469: C97.1 U2.31(P3[2])
N17133474: C130.1 U2.53(P0[4])
N17133557: R35.2 U2.22(P15[6]_D+)
N17133559: R34.2 U2.23(P15[7]_D-)
N17734371: C28.1 R26.2 U3.31(VBUS)
N17831172: Q2.2(S) Q3.2(S) Q4.2(S) R193.1
N17831185: D10.K(CATHODE) Q2.1(G) R193.2
N17831187: Q2.3(D) Q4.1(G) R195.2
N18103700: C67.1 U19.1(PMID)
N18103720: C9.1 L8.1 U19.23(SW) U19.24(SW)
N18103734: C9.2 U19.2(BOOT)
N18103773: R92.1 R98.2 U19.15(VDPM)
N18103970: R105.1 U19.12(ISET)
N18115594: R46.2 R50.1 R51.2 U10.4(ADJ)
N18115805: R48.1 SW5.1
N18115822: R51.1 SW5.3
N18115824: SW5.4 U27.7(RH)
N18116972: LED6.K(CATHODE) R102.2
N18117036: LED4.A(ANODE) R57.2
N18205136: R137.2 R139.1 R140.2 R144.1
N18205137: Q1.4(G1) R143.2
N18205161: Q1.1(S2) Q1.3(S1) R139.2 TP39.1
N18205190: Q1.2(G2) R138.2
N18323131: D9.A(ANODE) U31.9(VOUT) U31.10(VOUT)
N18323163: R185.2 U31.5(ILIM)
N18323191: C146.2 U31.3(SS)
N18323606: R87.1 U13.1(GND)
N18323726: C49.1 J16.2 U13.3(OUT)
N18429699: R100.1 R104.2 U17.11(~{OE})
N18439299: L9.1 U1.J2(VIND1)
N18439327: L9.2 U1.K2(VIND2)
N18697642: LED7.A(ANODE) R75.2
N18699542: LED1.A(ANODE) R56.2
N18699562: LED2.A(ANODE) R54.2
N18699568: LED3.A(ANODE) R55.2
N18713395: C44.2 R49.2 U8.3(EN)
N18777793: C91.1 R118.2 R125.2 U23.4(EN)
N18781968: R77.2 U17.2(A0)
N18781971: R81.2 U17.3(A1)
N18781974: R85.2 U17.4(A2)
N18782191: R88.2 U17.6(A4)
N18782194: R93.2 U17.7(A5)
N18810466: J8.1 R148.1 R151.1 U25.4(IN-) U25.5(IN-)
N18920306: R41.1 R42.2 U9.4(ADJ)

Not connected (* = marked no-connect by the designer): J12 7*; U2 6(IND)*; U3 4(V5V)* 6(VCONN)* 11(P1.6)* 12(P1.4)* 13(P1.5)* 14(P1.7)* 21(DPLUS)* 22(DMINUS)* 23(P2.4)* 27(P0.0)* 28(P0.1)* 29(VBUS_C_CTRL1)* 30(VBUS_C_CTRL0)*; U13 4(ST)*; U17 8(A6)* 9(A7)* 12(B7)* 13(B6)* 21(DAP)*; U19 10(~{PG})* 11(BGATE)*; U25 1(NC1)* 6(NC2)* 7(NC3)* 8(NC4)*; U31 7(~{PG})* 8(~{FLG})*

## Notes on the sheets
sheet 1
- CY8CKIT-062-WiFi-BT   PSoC™ 6  Wi-Fi-Bluetooth® Pioneer Kit
- CONTENTS
- PAGE
- DESCRIPTION
- 01
- Title & Table of Contents
- 02
- Block Diagram
- 03
- 5V Buck-Boost Regulator
- 04
- Variable Regulator, LiPo Battery Charger
- 05
- KitProg3 Controller
- 06
- Kitprog3 Power & Headers
- 07
- Type-C Controller
- 08
- Type-C Power Path
- 09
- PSoC 6 Power Connection
- 10
- PSoC 6 Signals
- 11
- On-board Peripherals
- 12
- Expansion Headers & Memory
- 13
- USB Host & Device Interface
- WiFi/BT Module Interface
- 14
- 15
- Revision History
- Drawing Numbers
- PCBA
- PCB
- FAB DRW
- ASSY DRW
- SCH DRW
sheet 3
- LiPo Battery Charger
- Charging LED
- Power LED
- Reverse Voltage Protection
- BAT NTC I/P
- Battery Connector
- +
- -
- 1.8V - 3.3V Variable Regulator
- 3.3V Regulator
- 600mA
- 600mA
- SW5
- Source
- POS1
- 1.8V
- POS2
- 3.3V
- POS3
- Variable (1.8-3.3V)
sheet 4
- PSoC 5LP based KitProg3
- Decoupling Capacitors
- SAR Bypass
  Capacitor
- Supply for PSoC 5LP
- Note: Supply for PSoC 5LP
  (KitProg3) is enabled only when
  powered from KitProg3 USB port
- I2C Interface
- UART Interface
- Del-Sig Bypass
  Capacitor
- PSoC 5LP Status LEDs
- PSoC 5LP User Switches
- KitProg3 HW Revision
- Bit 0
- Programming
  Mode
- Bit 1
- Bit 2
- Bit 3
- Bit 4
- Custom App
- ID = 0x02
- Note: GND is read as binary
  "1" and floating as "0"
sheet 5
- Target PSoC Program/Debug Header
- ETM Header
- PSoC 6 SWD/JTAG Interface
- Remove R182, R183, R194
  to isolate KitProg3
- Remove R190, R191, R192 for
  programming external target
- PSoC 5LP Custom Application Header
- PSoC 5LP GPIO Expansion Header
- Voltage Monitoring
- P5LP15_1
- CUSTOM
- CUSTOM
- P5LP15_2
- P5LP12_0
- CUSTOM
- P5LP15_3
- CUSTOM
- CUSTOM
- P5LP12_5
- P5LP12_1
- P5LP1_6
- SUSPEND
- CUSTOM
- P5LP12_7
- CUSTOM
- P5LP12_6
- CUSTOM
- Program/Debug Overvoltage Protection
- Level Translator for SPI and UART flow control
sheet 6
- CCG3 Supply Selection
- CCG3  USB Type-C Controller
- Decoupling Capacitors
- VBUS & VIN Voltage Monitoring
- I2C Bootloader
- LiPo Battery Charger Pull Up
- CCG3 Programming
- Output Indication
sheet 7
- VBUS Provider Path
- CCG3 Provider Path 'OR'ing
- CCG3 Consumer Path
sheet 8
- PSoC 6 Power
- Decoupling Capacitors
- VDD Current Measurement
- (CURRENT SENSE)
- Default, loaded
- (GND)
- Voltage Follower
- PSoC 6 VDDUSB Enable
- Note: This circuit is to reduce the leakage current in VTARG domain
